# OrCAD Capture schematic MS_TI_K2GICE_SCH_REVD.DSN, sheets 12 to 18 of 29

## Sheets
12 P12_K2G_ICE_SPI_FLASH: size C; title: QSPI_FLASH
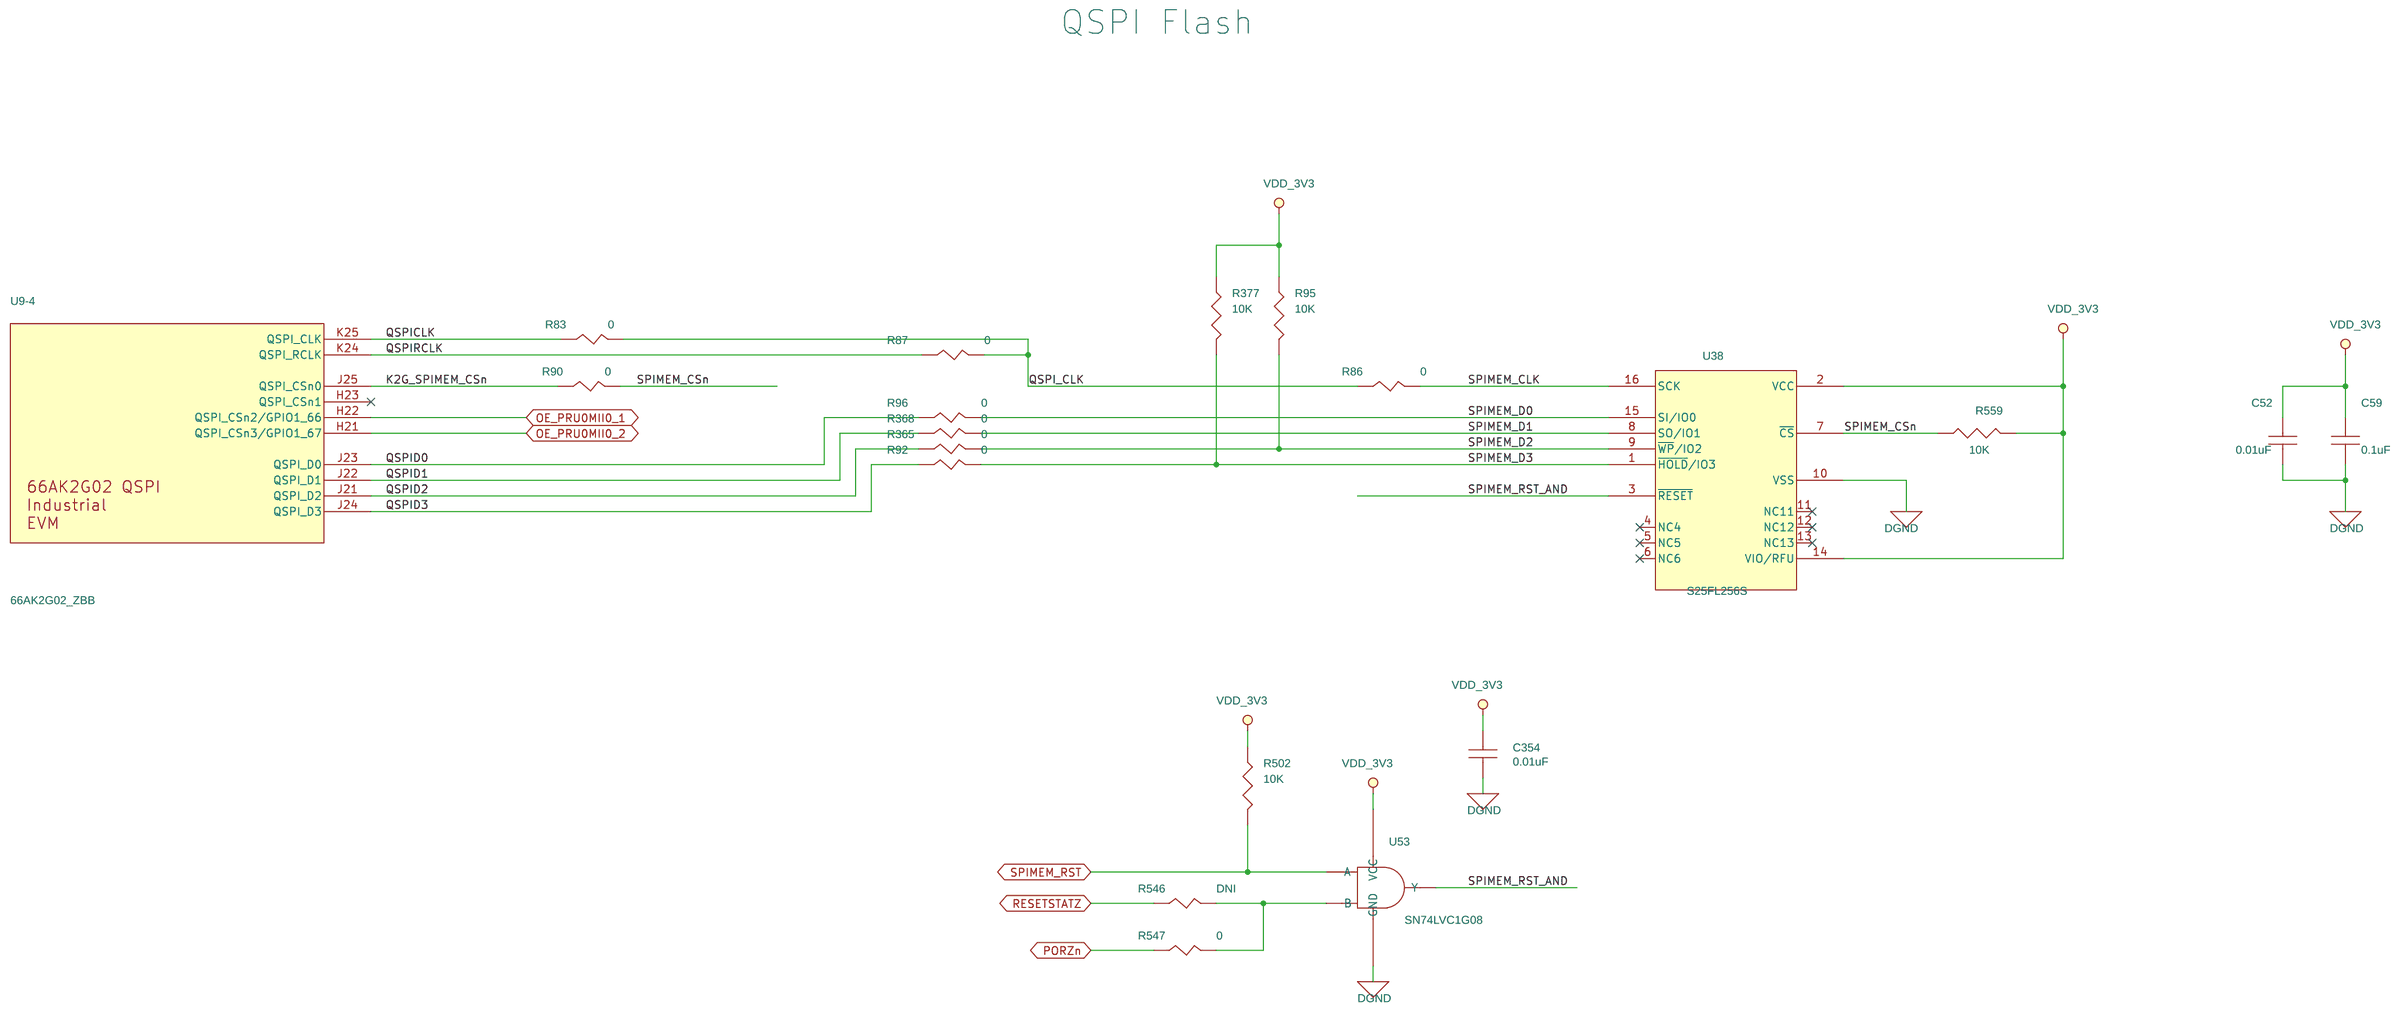
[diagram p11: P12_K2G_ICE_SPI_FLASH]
13 P13_K2G_ICE_GigEthernet: size C; title: GIGABIT ETHERNET
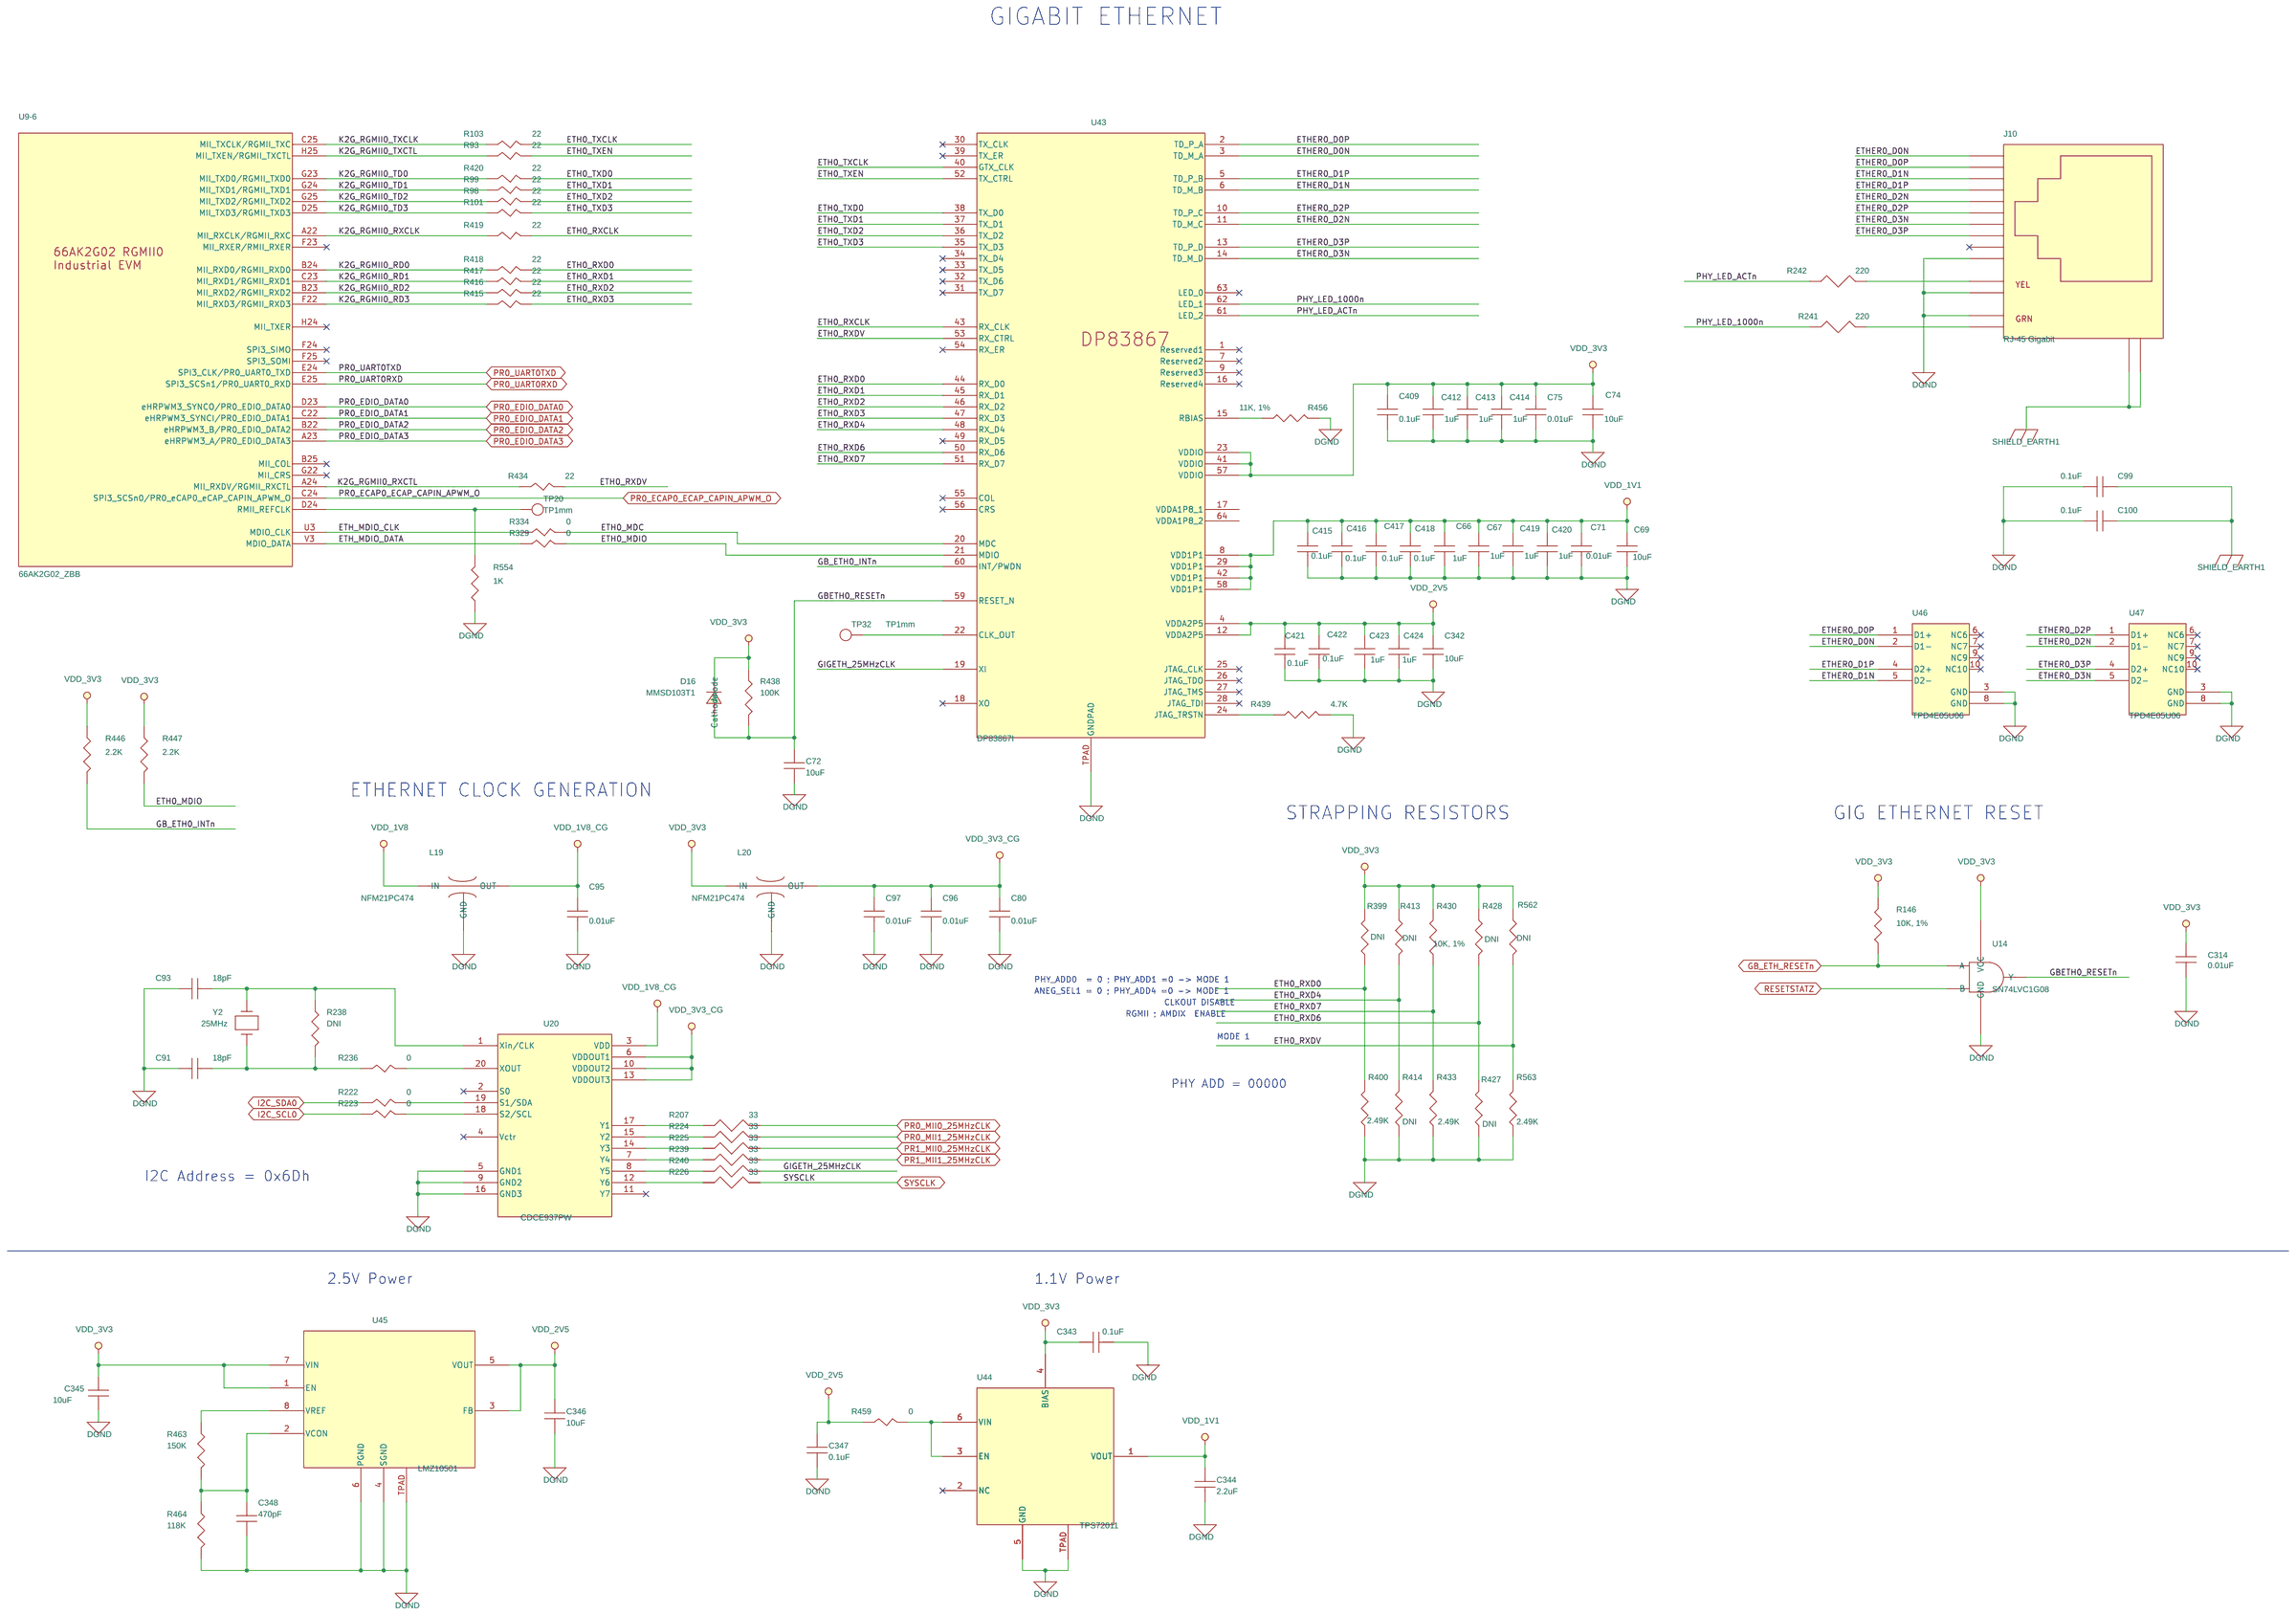
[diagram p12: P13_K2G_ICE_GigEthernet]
14 P14_K2G_ICE_PRU0MII0_Ethernet 0: size C; title: PRU0MII0_Ethernet 0
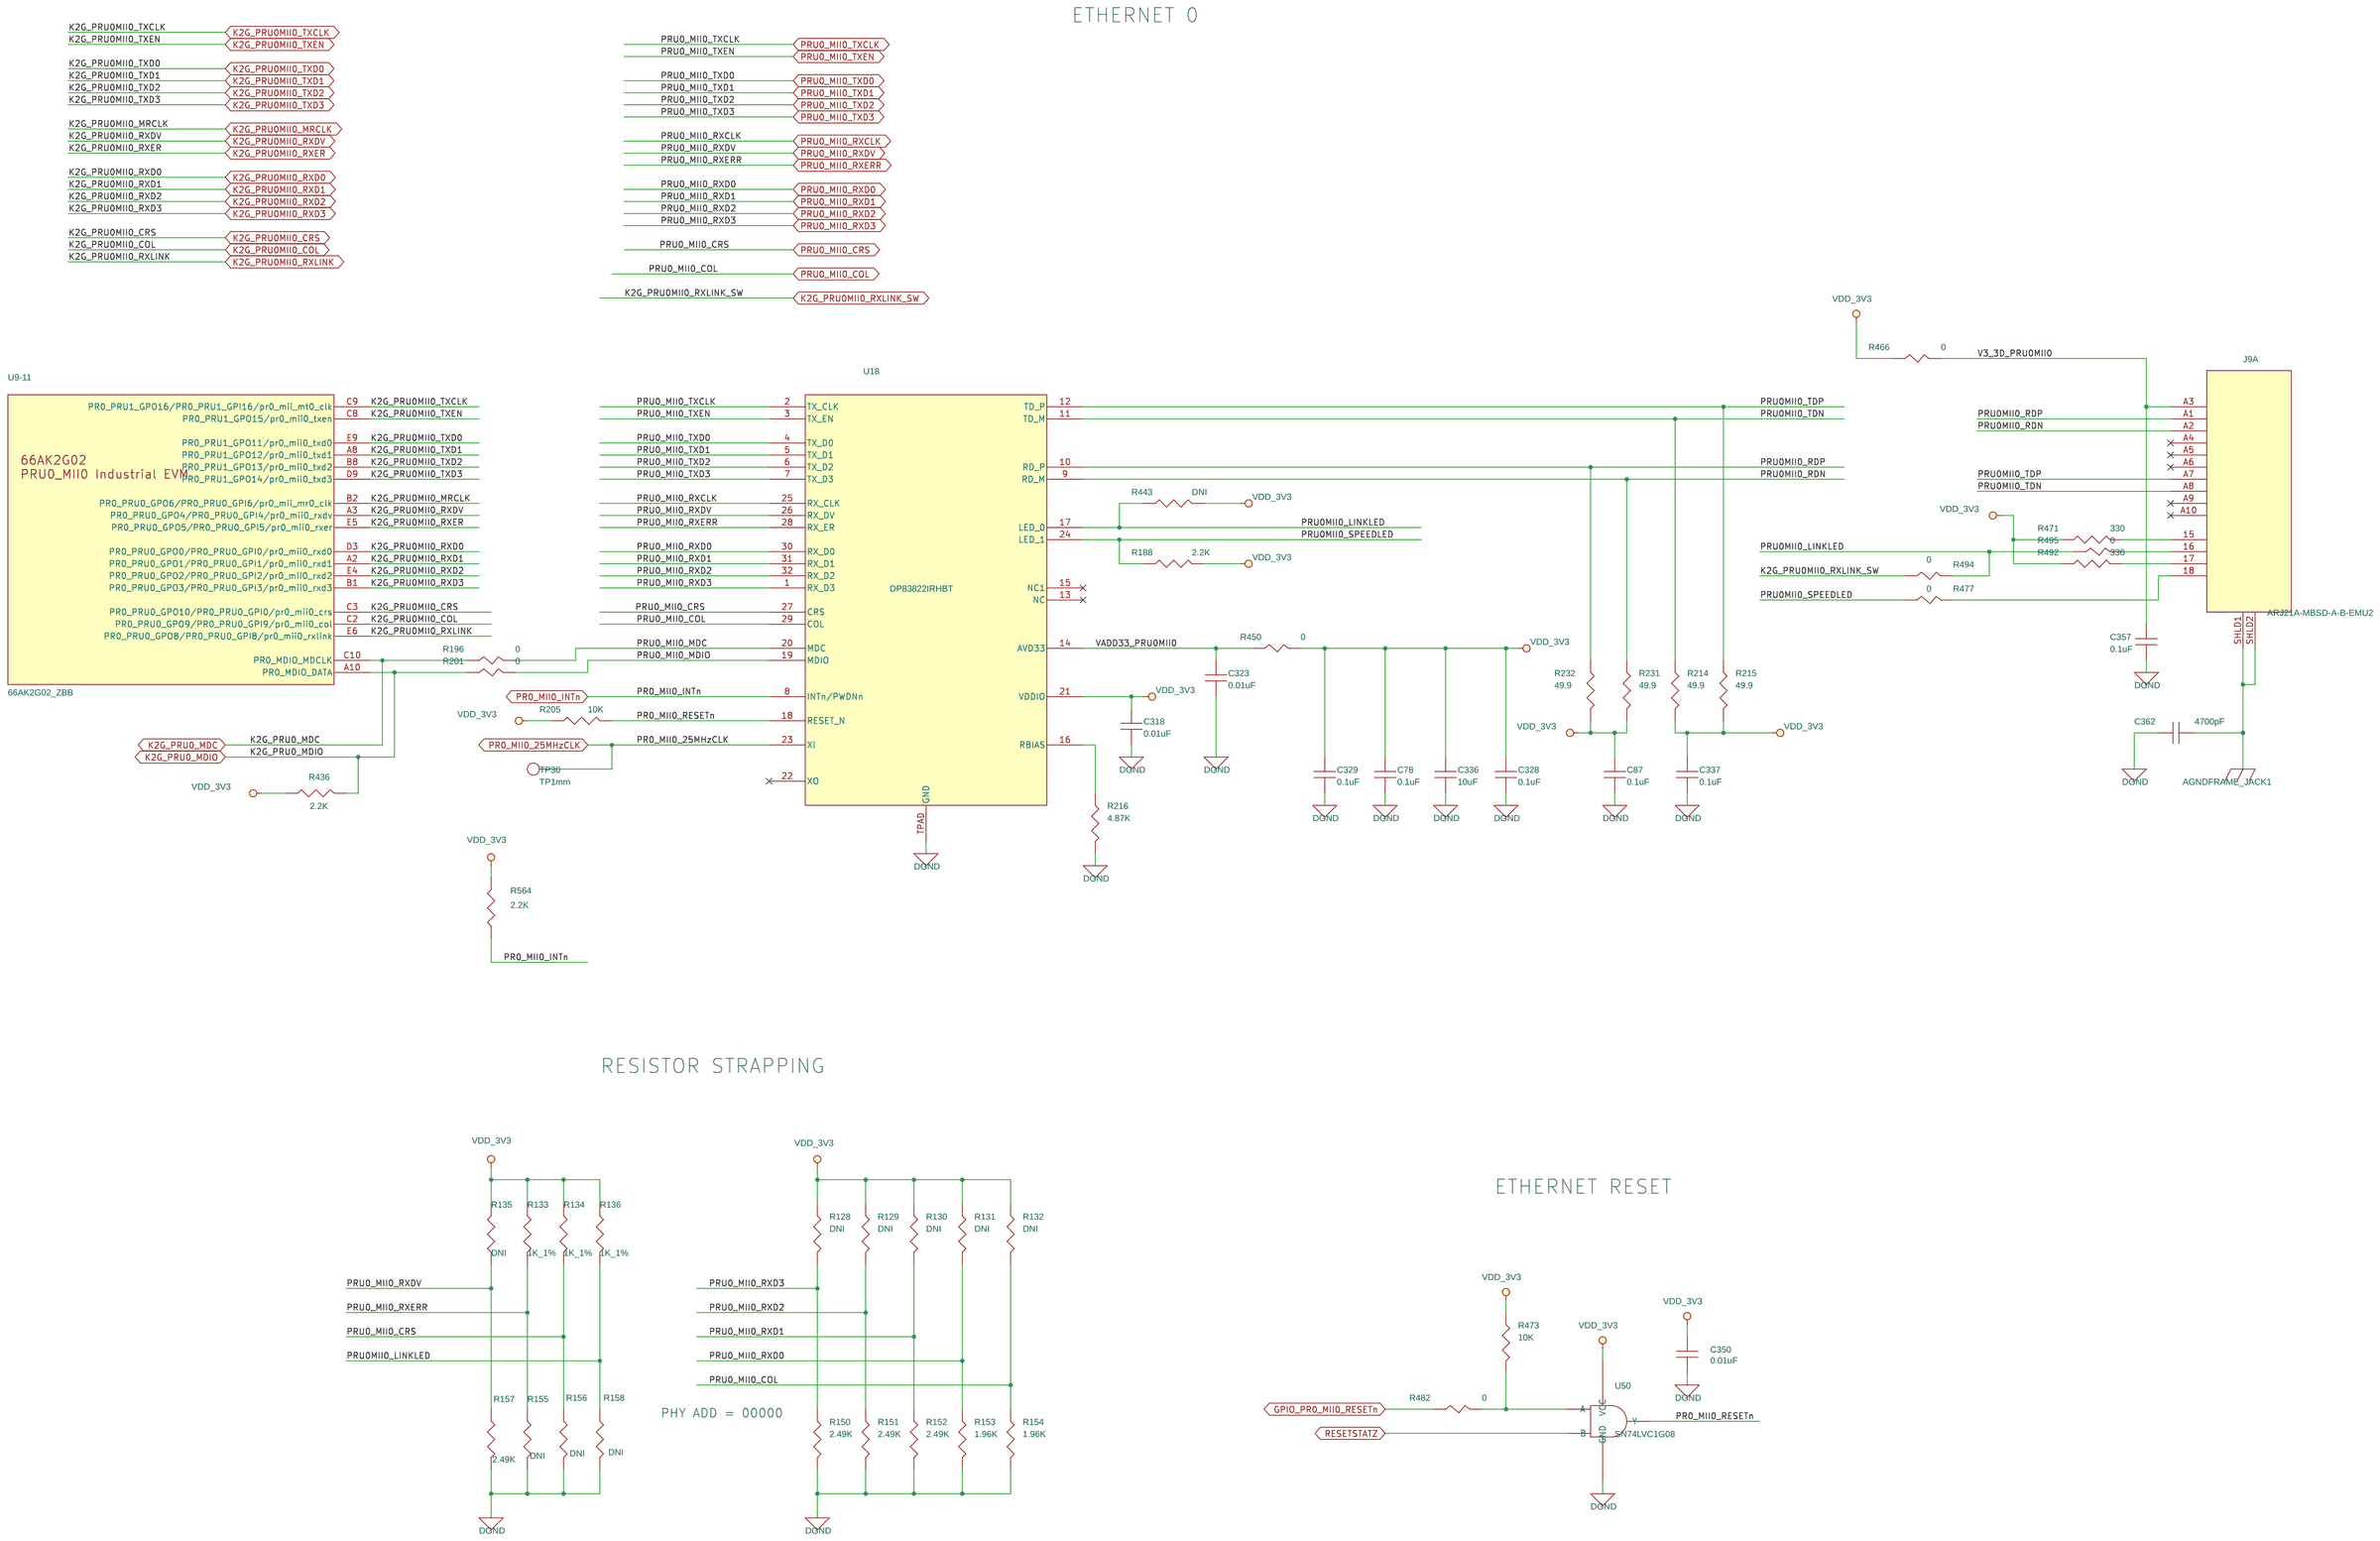
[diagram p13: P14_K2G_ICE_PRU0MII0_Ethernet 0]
15 P15_K2G_ICE_PRU0MII1_Ethernet 1: size C; title: PRU0MII1_Ethernet 1
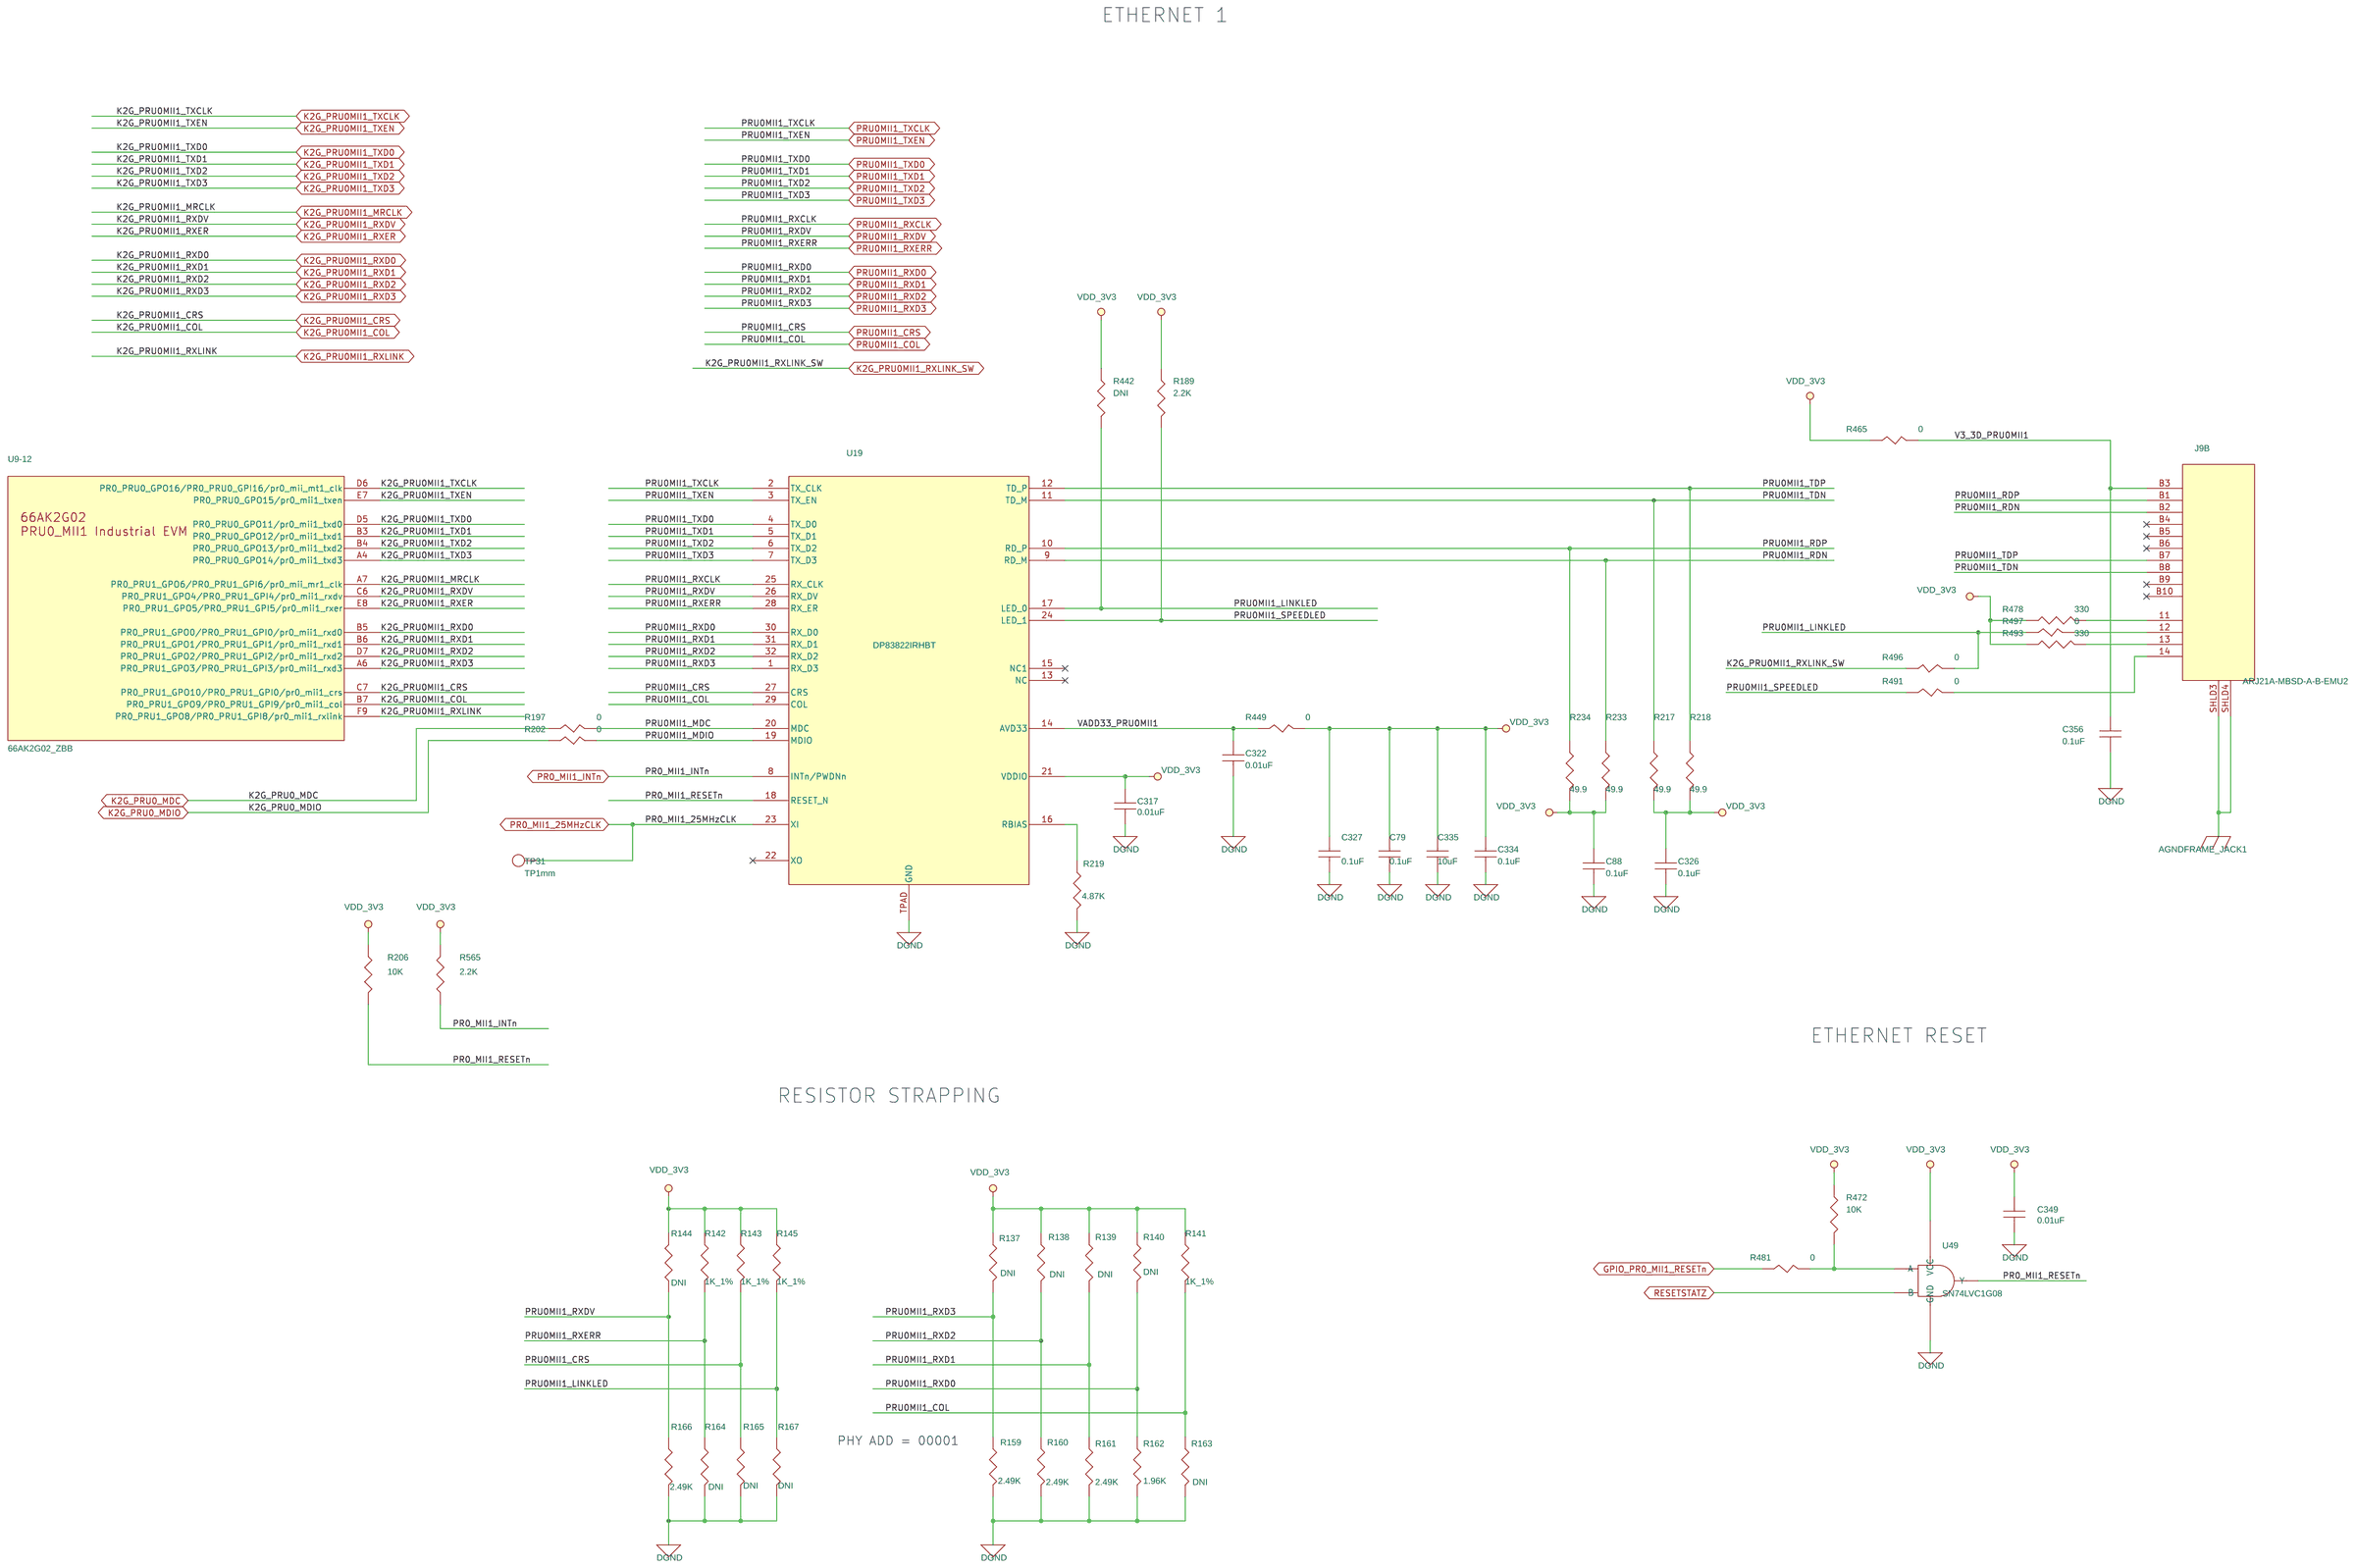
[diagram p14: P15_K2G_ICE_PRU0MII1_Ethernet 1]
16 P16_K2G_ICE_PRU1MII0_Ethernet 2: size C; title: PRU1MII0_Ethernet 2
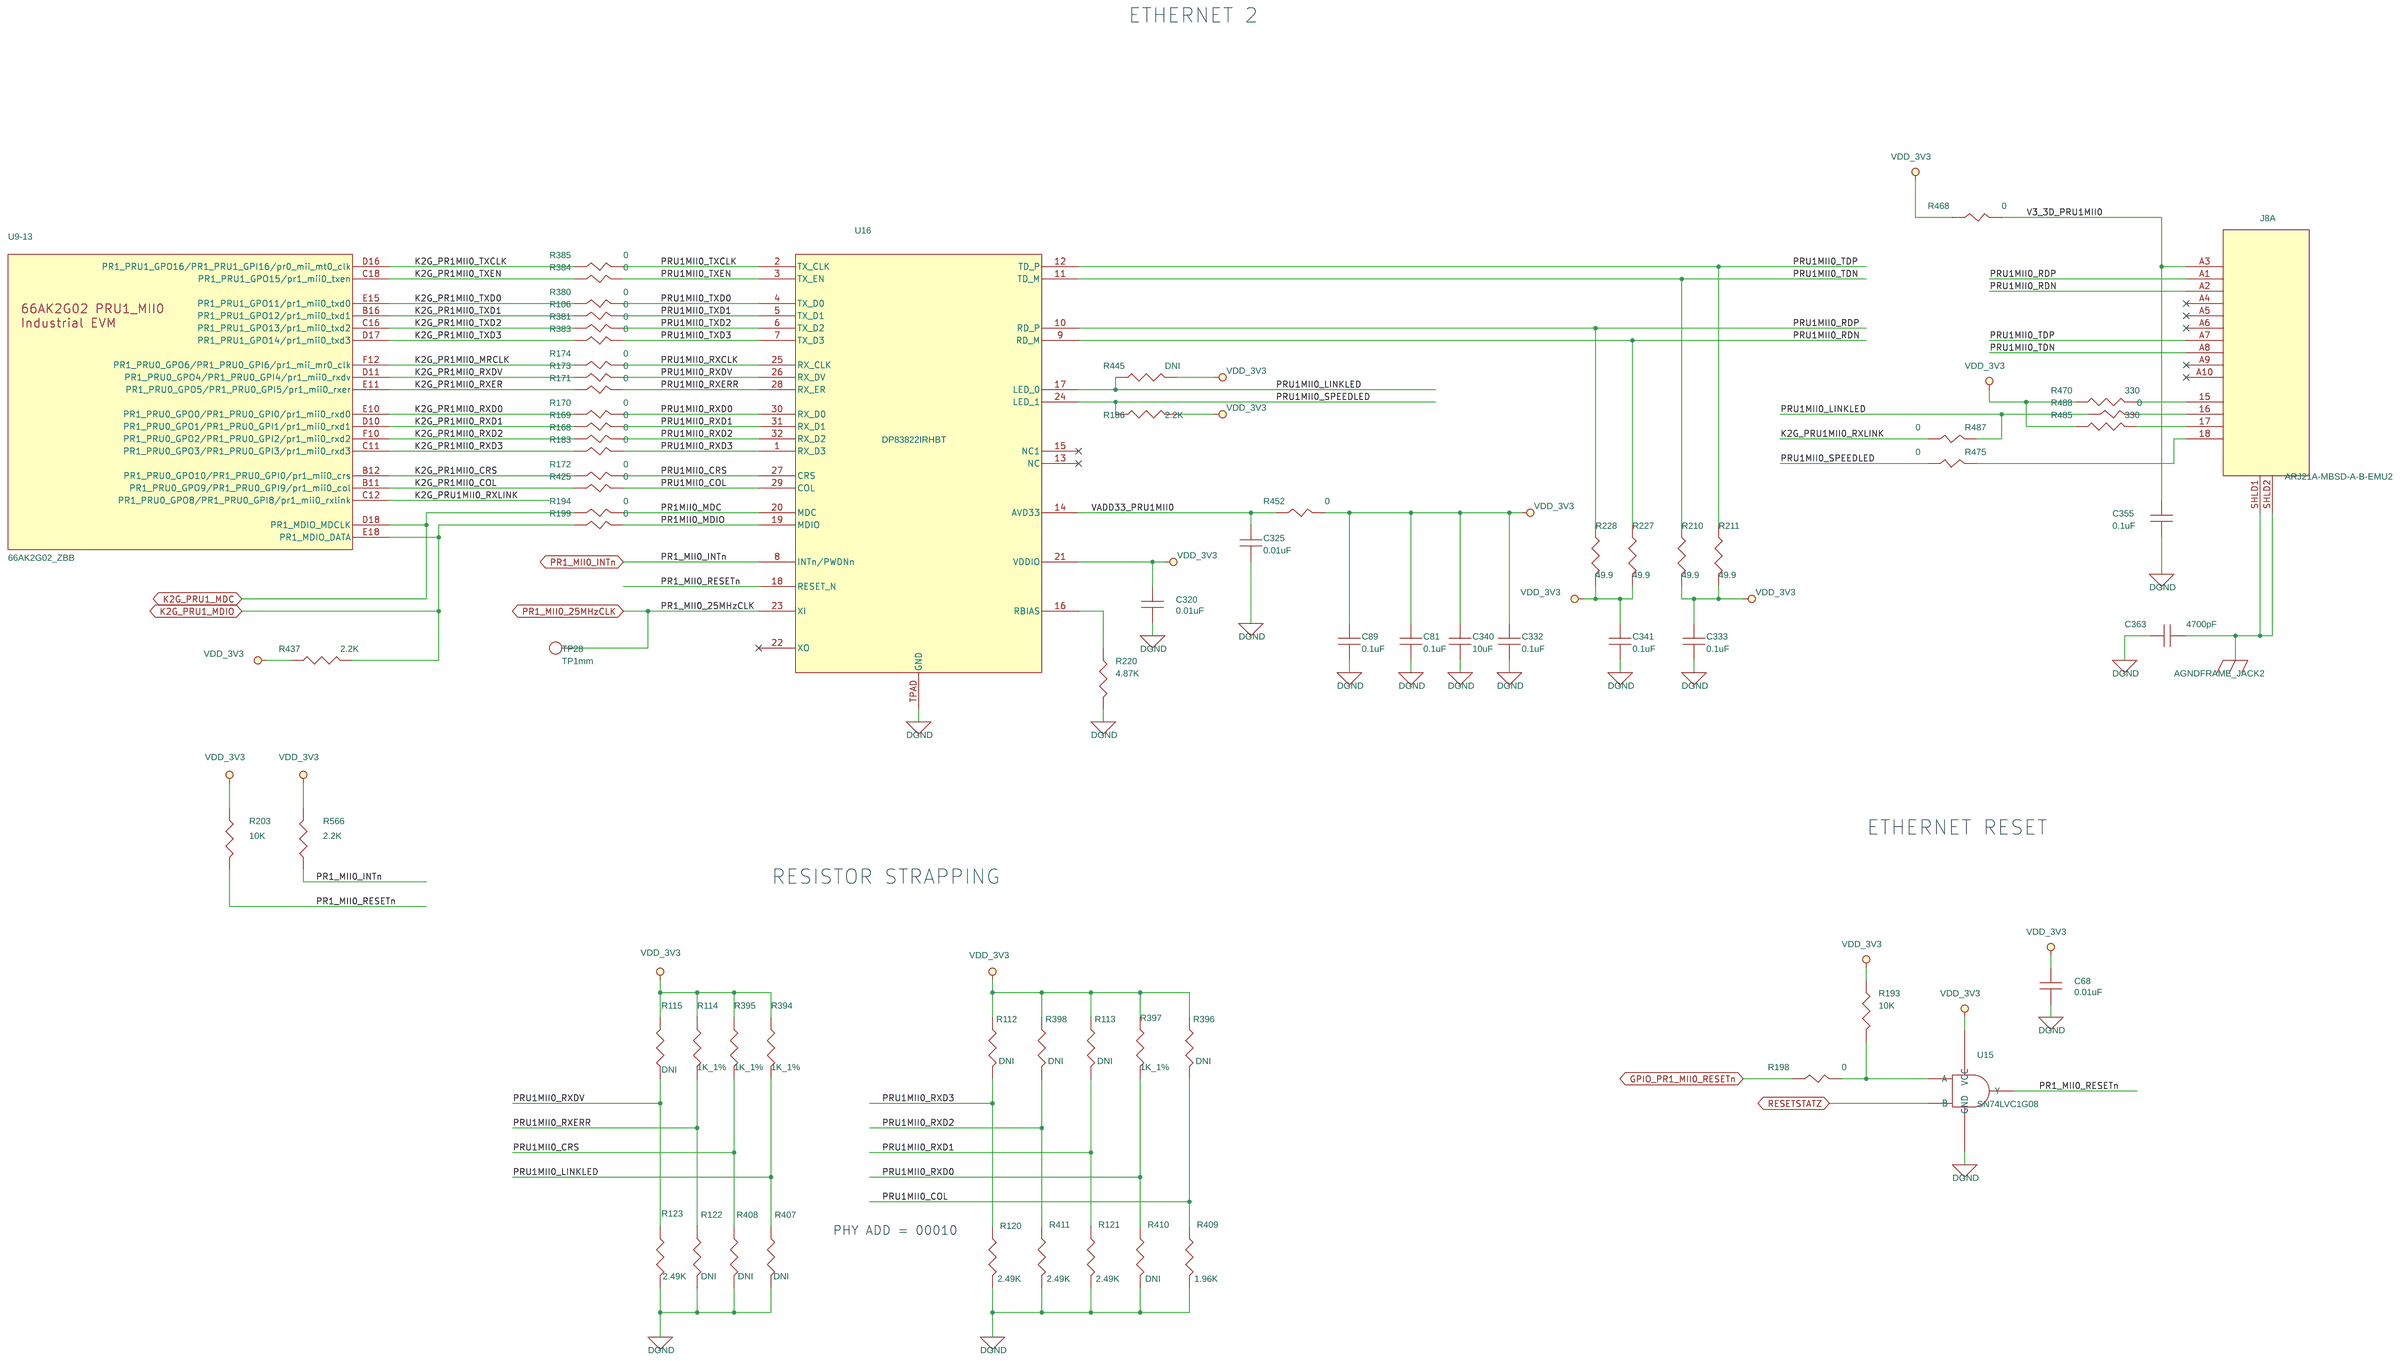
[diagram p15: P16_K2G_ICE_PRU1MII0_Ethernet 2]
17 P17_K2G_ICE_PRU1MII1_Ethernet 3: size C; title: PRU1MII1_Ethernet 3
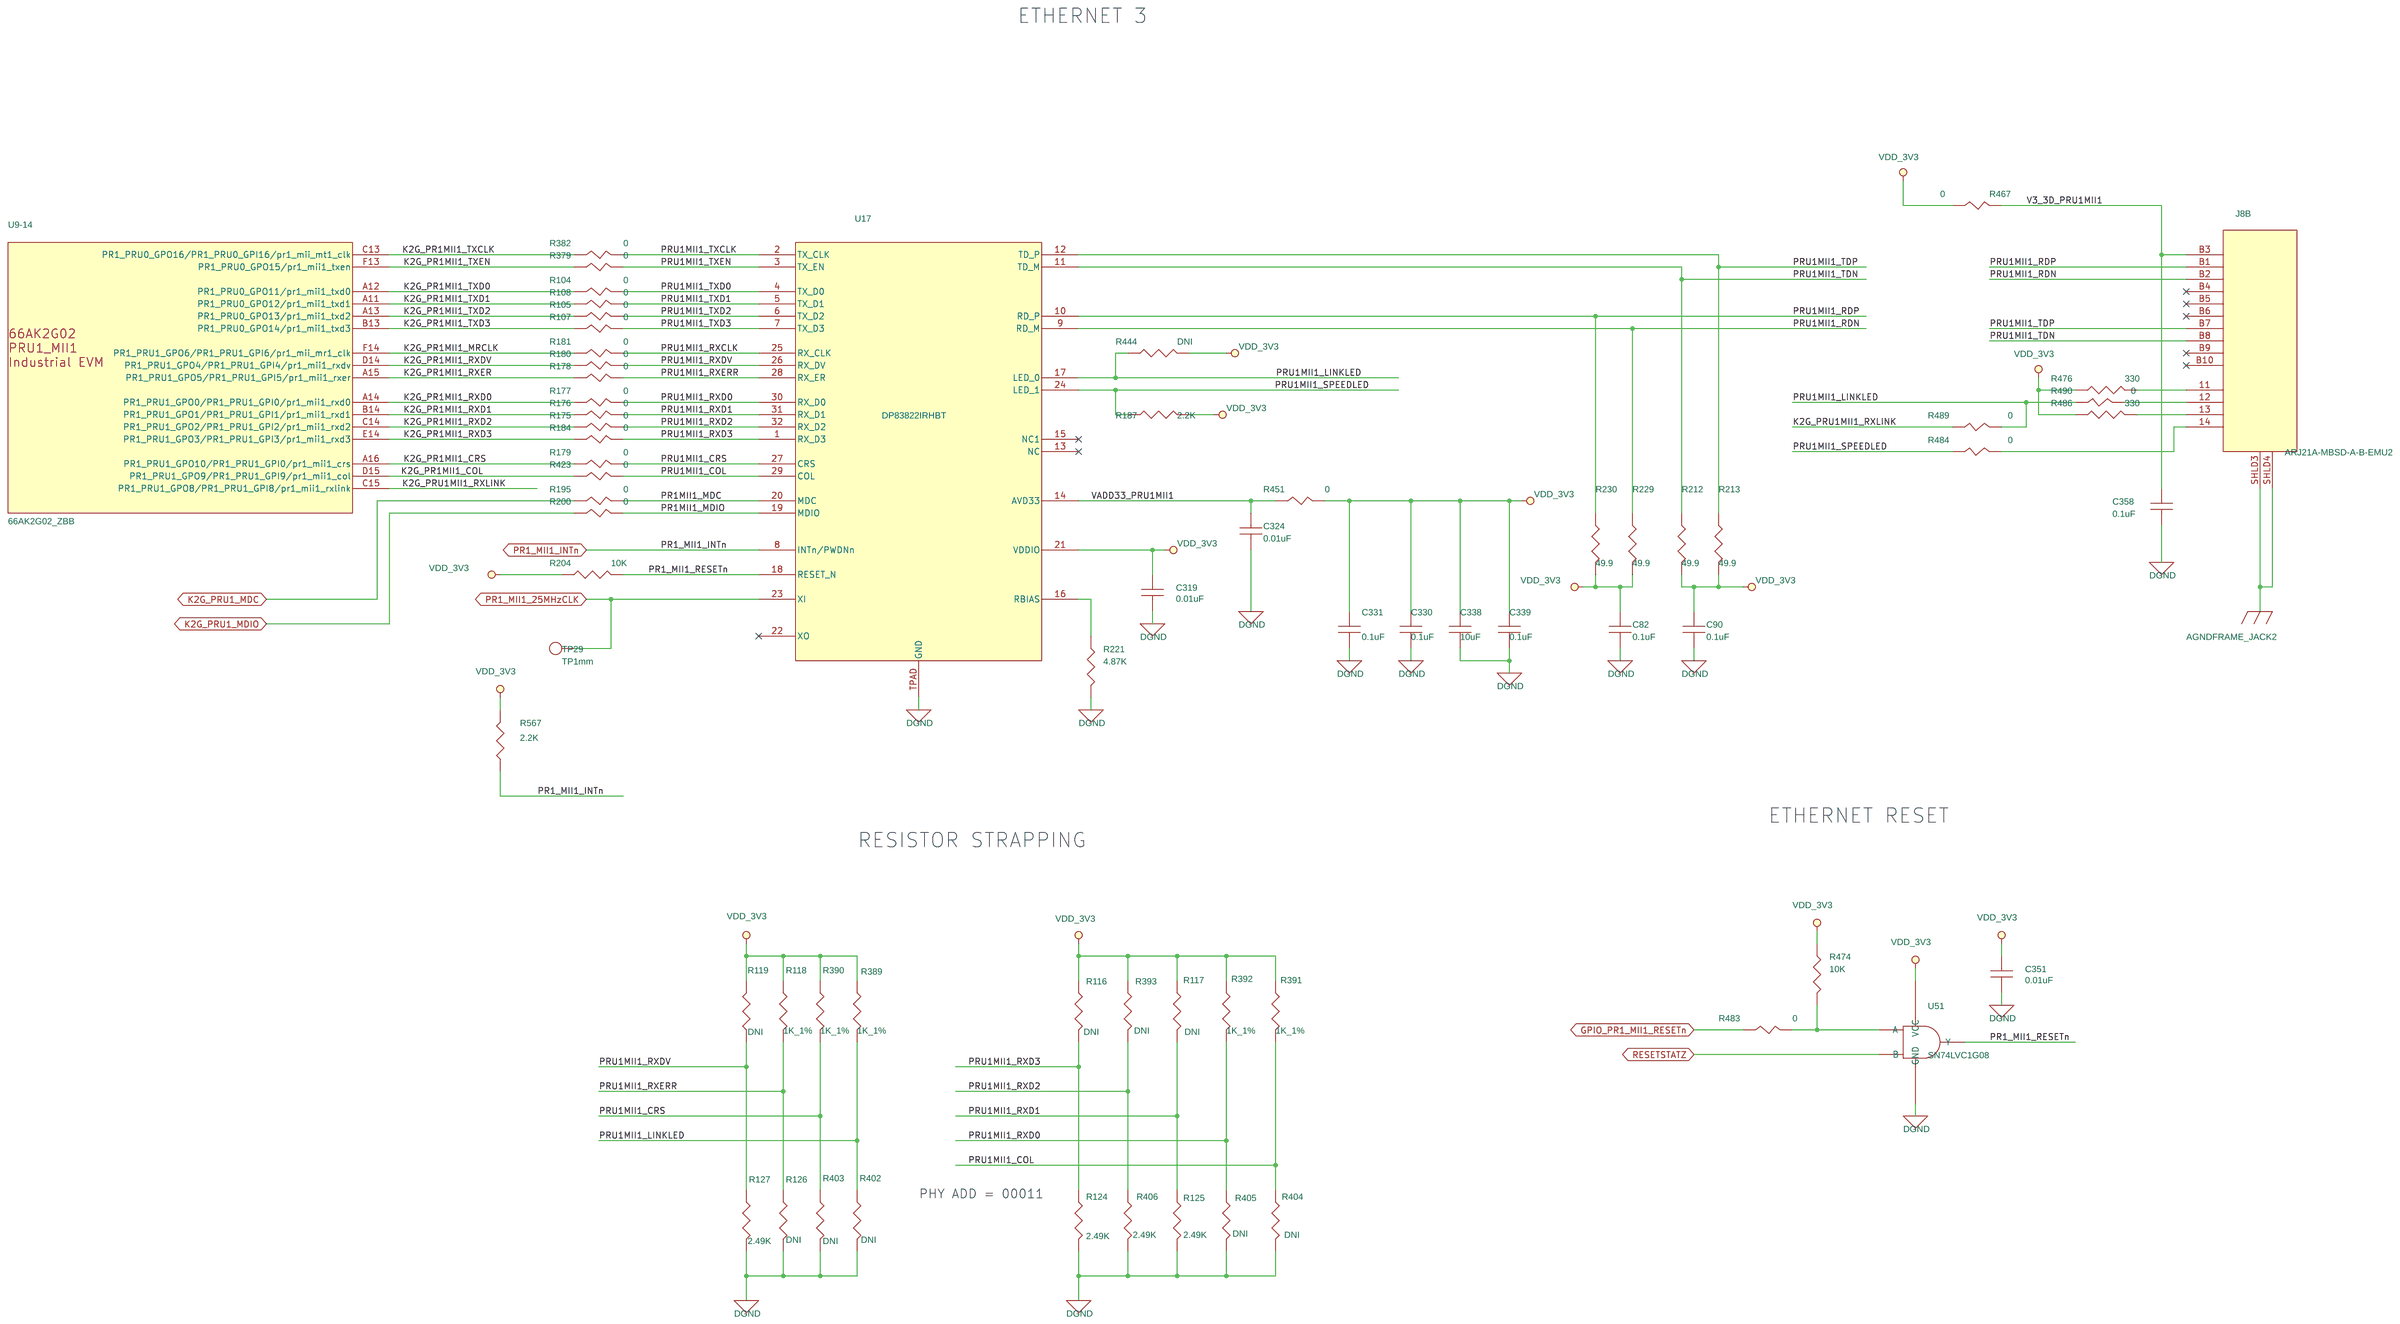
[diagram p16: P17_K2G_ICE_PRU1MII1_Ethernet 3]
18 P18_K2G_ICE_SDMMC: size C; title: SDMMC
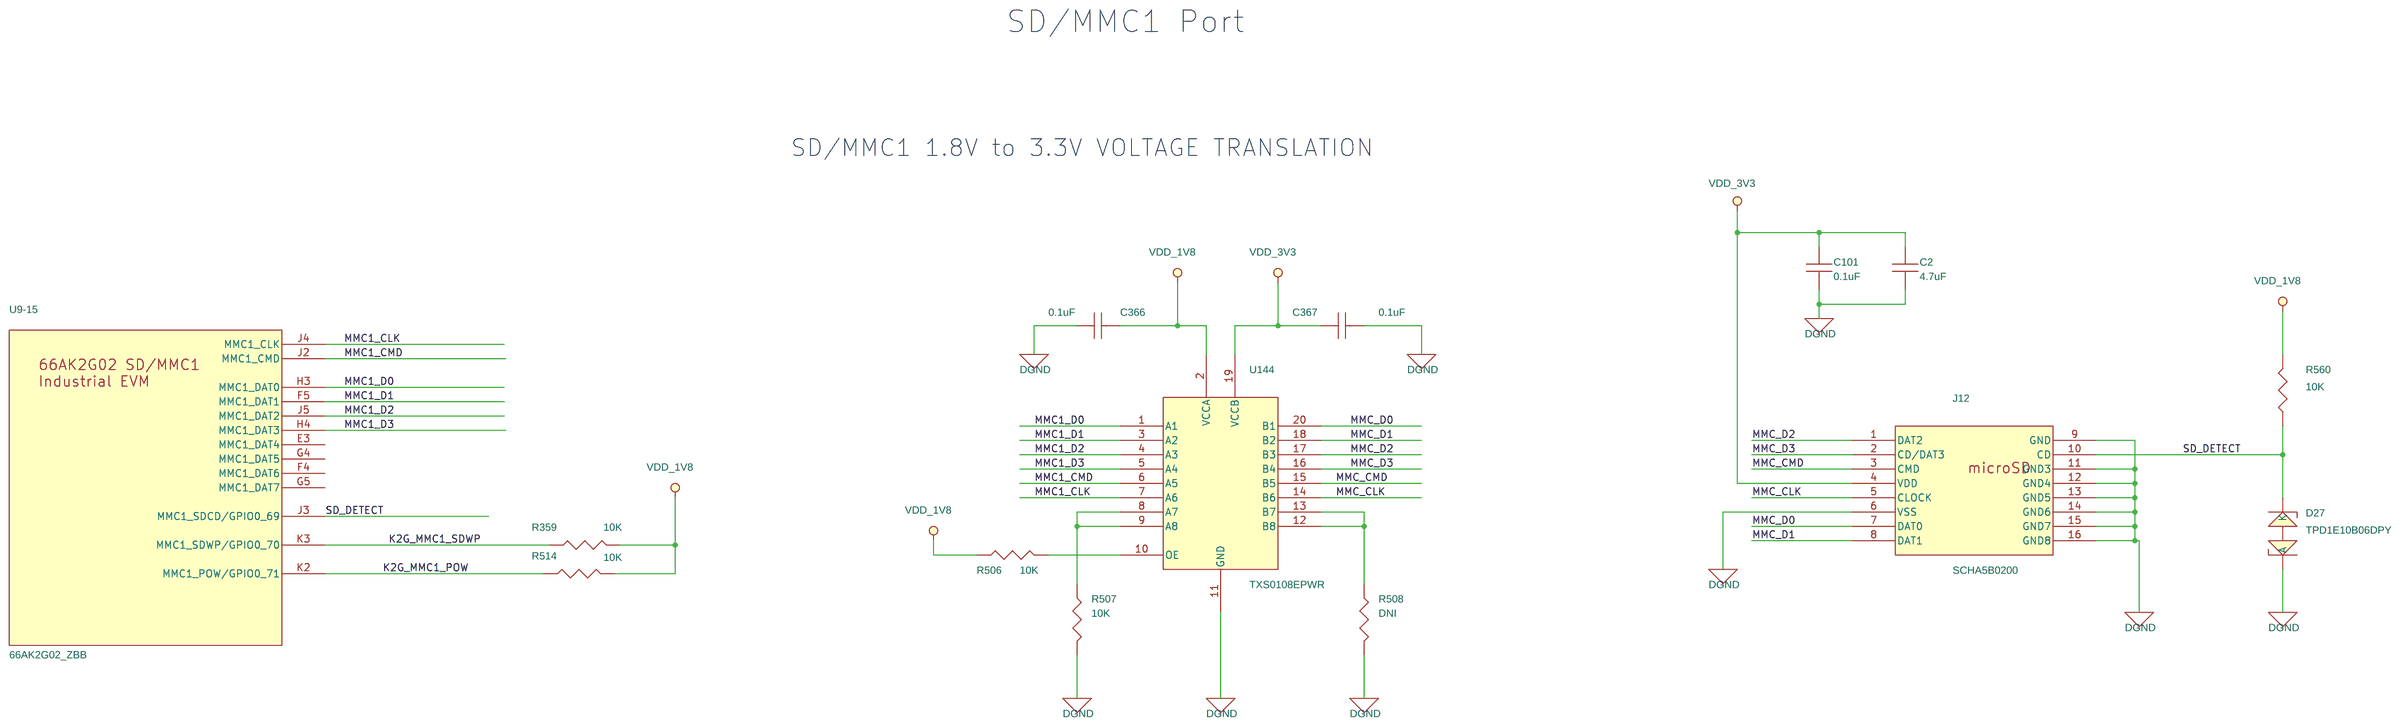
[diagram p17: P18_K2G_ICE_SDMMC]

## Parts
sheet P12_K2G_ICE_SPI_FLASH
C52  0.01uF  [SM-7351-CAP-0402]
C59  0.1uF  [SM-7351-CAP-0402]
C354  0.01uF  [SM-7351-CAP-0402]
R83  0  [SM-7351-RES-0402]
R86  0  [SM-7351-RES-0402]
R87  0  [SM-7351-RES-0402]
R90  0  [SM-7351-RES-0402]
R92  0  [SM-7351-RES-0402]
R95  10K  [SM-7351-RES-0402]
R96  0  [SM-7351-RES-0402]
R365  0  [SM-7351-RES-0402]
R368  0  [SM-7351-RES-0402]
R377  10K  [SM-7351-RES-0402]
R502  10K  [SM-7351-RES-0402]
R546  DNI  [SM-7351-RES-0402]
R547  0  [SM-7351-RES-0402]
R559  10K  [SM-7351-RES-0402]
U38  S25FL256S  [soic_16pin_dw]
U53  SN74LVC1G08  [sm-so-sc70-5]
sheet P13_K2G_ICE_GigEthernet
C66  1uF  [SM-7351-CAP-0402]
C67  1uF  [SM-7351-CAP-0402]
C69  10uF  [SM-7351-CAP-0805]
C71  0.01uF  [SM-7351-CAP-0402]
C72  10uF  [SM-7351-CAP-0805]
C74  10uF  [SM-7351-CAP-0805]
C75  0.01uF  [SM-7351-CAP-0402]
C80  0.01uF  [SM-7351-CAP-0402]
C91  18pF  [SM-7351-CAP-0402]
C93  18pF  [SM-7351-CAP-0402]
C95  0.01uF  [SM-7351-CAP-0402]
C96  0.01uF  [SM-7351-CAP-0402]
C97  0.01uF  [SM-7351-CAP-0402]
C99  0.1uF  [SM-7351-CAP-0402]
C100  0.1uF  [SM-7351-CAP-0402]
C314  0.01uF  [SM-7351-CAP-0402]
C342  10uF  [SM-7351-CAP-0805]
C343  0.1uF  [SM-7351-CAP-0402]
C344  2.2uF  [SM-7351-CAP-0603]
C345  10uF  [SM-7351-CAP-0805]
C346  10uF  [SM-7351-CAP-0805]
C347  0.1uF  [SM-7351-CAP-0402]
C348  470pF  [SM-7351-CAP-0402]
C409  0.1uF  [SM-7351-CAP-0402]
C412  1uF  [SM-7351-CAP-0402]
C413  1uF  [SM-7351-CAP-0402]
C414  1uF  [SM-7351-CAP-0402]
C415  0.1uF  [SM-7351-CAP-0402]
C416  0.1uF  [SM-7351-CAP-0402]
C417  0.1uF  [SM-7351-CAP-0402]
C418  0.1uF  [SM-7351-CAP-0402]
C419  1uF  [SM-7351-CAP-0402]
C420  1uF  [SM-7351-CAP-0402]
C421  0.1uF  [SM-7351-CAP-0402]
C422  0.1uF  [SM-7351-CAP-0402]
C423  1uF  [SM-7351-CAP-0402]
C424  1uF  [SM-7351-CAP-0402]
D16  MMSD103T1  [sod-123]
J10  RJ-45 Gigabit  [CNRJ45-1X1WLED-598M]
L19  NFM21PC474  [FILT-NFM21PC]
L20  NFM21PC474  [FILT-NFM21PC]
R93  22  [SM-7351-RES-0402]
R98  22  [SM-7351-RES-0402]
R99  22  [SM-7351-RES-0402]
R101  22  [SM-7351-RES-0402]
R103  22  [SM-7351-RES-0402]
R146  10K, 1%  [SM-7351-RES-0402]
R207  33  [SM-7351-RES-0402]
R222  0  [SM-7351-RES-0402]
R223  0  [SM-7351-RES-0402]
R224  33  [SM-7351-RES-0402]
R225  33  [SM-7351-RES-0402]
R226  33  [SM-7351-RES-0402]
R236  0  [SM-7351-RES-0402]
R238  DNI  [SM-7351-RES-0402]
R239  33  [SM-7351-RES-0402]
R240  33  [SM-7351-RES-0402]
R241  220  [SM-7351-RES-0402]
R242  220  [SM-7351-RES-0402]
R329  0  [SM-7351-RES-0402]
R334  0  [SM-7351-RES-0402]
R399  DNI  [SM-7351-RES-0402]
R400  2.49K  [SM-7351-RES-0402]
R413  DNI  [SM-7351-RES-0402]
R414  DNI  [SM-7351-RES-0402]
R415  22  [SM-7351-RES-0402]
R416  22  [SM-7351-RES-0402]
R417  22  [SM-7351-RES-0402]
R418  22  [SM-7351-RES-0402]
R419  22  [SM-7351-RES-0402]
R420  22  [SM-7351-RES-0402]
R427  DNI  [SM-7351-RES-0402]
R428  DNI  [SM-7351-RES-0402]
R430  10K, 1%  [SM-7351-RES-0402]
R433  2.49K  [SM-7351-RES-0402]
R434  22  [SM-7351-RES-0402]
R438  100K  [SM-7351-RES-0402]
R439  4.7K  [SM-7351-RES-0402]
R446  2.2K  [sm-7351-res-0402]
R447  2.2K  [sm-7351-res-0402]
R456  11K, 1%  [SM-7351-RES-0402]
R459  0  [SM-7351-RES-1210]
R463  150K  [SM-7351-RES-0402]
R464  118K  [SM-7351-RES-0402]
R554  1K  [SM-7351-RES-0402]
R562  DNI  [SM-7351-RES-0402]
R563  2.49K  [SM-7351-RES-0402]
TP20  TP1mm  [tp_smd1mmcircle]
TP32  TP1mm  [tp_smd1mmcircle]
U14  SN74LVC1G08  [sm-so-sc70-5]
U20  CDCE937PW  [U_20_PW]
U43  DP83867I  [QFP10X10-64-47M]
U44  TPS72011  [SON2X2-6]
U45  LMZ10501  [LLP3X2-8-59M]
U46  TPD4E05U06  [USON2X1-10-22M]
U47  TPD4E05U06  [USON2X1-10-22M]
Y2  25MHz  [SM_OSC_ABM3]
sheet P14_K2G_ICE_PRU0MII0_Ethernet 0
C78  0.1uF  [SM-7351-CAP-0402]
C87  0.1uF  [SM-7351-CAP-0402]
C318  0.01uF  [SM-7351-CAP-0402]
C323  0.01uF  [SM-7351-CAP-0402]
C328  0.1uF  [SM-7351-CAP-0402]
C329  0.1uF  [SM-7351-CAP-0402]
C336  10uF  [SM-7351-CAP-0805]
C337  0.1uF  [SM-7351-CAP-0402]
C350  0.01uF  [SM-7351-CAP-0402]
C357  0.1uF  [SM-7351-CAP-0402]
C362  4700pF  [SM-7351-CAP-0402]
J9  ARJ21A-MBSD-A-B-EMU2  [CNARJ21A-MB]  (sections A,B)
R128  DNI  [SM-7351-RES-0402]
R129  DNI  [SM-7351-RES-0402]
R130  DNI  [RES0402]
R131  DNI  [SM-7351-RES-0402]
R132  DNI  [SM-7351-RES-0402]
R133  1K_1%  [SM-7351-RES-0402]
R134  1K_1%  [SM-7351-RES-0402]
R135  DNI  [SM-7351-RES-0402]
R136  1K_1%  [SM-7351-RES-0402]
R150  2.49K  [SM-7351-RES-0402]
R151  2.49K  [SM-7351-RES-0402]
R152  2.49K  [SM-7351-RES-0402]
R153  1.96K  [SM-7351-RES-0402]
R154  1.96K  [SM-7351-RES-0402]
R155  DNI  [SM-7351-RES-0402]
R156  DNI  [SM-7351-RES-0402]
R157  2.49K  [SM-7351-RES-0402]
R158  DNI  [SM-7351-RES-0402]
R188  2.2K  [sm-7351-res-0402]
R196  0  [SM-7351-RES-0402]
R201  0  [SM-7351-RES-0402]
R205  10K  [SM-7351-RES-0402]
R214  49.9  [SM-7351-RES-0402]
R215  49.9  [SM-7351-RES-0402]
R216  4.87K  [SM-7351-RES-0402]
R231  49.9  [SM-7351-RES-0402]
R232  49.9  [SM-7351-RES-0402]
R436  2.2K  [sm-7351-res-0402]
R443  DNI  [sm-7351-res-0402]
R450  0  [SM-7351-RES-0603]
R466  0  [SM-7351-RES-0402]
R471  330  [SM-7351-RES-0402]
R473  10K  [SM-7351-RES-0402]
R477  0  [SM-7351-RES-0402]
R482  0  [SM-7351-RES-0402]
R492  330  [SM-7351-RES-0402]
R494  0  [SM-7351-RES-0402]
R495  0  [SM-7351-RES-0402]
R564  2.2K  [sm-7351-res-0402]
TP30  TP1mm  [tp_smd1mmcircle]
U18  DP83822IRHBT  [qfn5x5-32-39m]
U50  SN74LVC1G08  [sm-so-sc70-5]
sheet P15_K2G_ICE_PRU0MII1_Ethernet 1
C79  0.1uF  [SM-7351-CAP-0402]
C88  0.1uF  [SM-7351-CAP-0402]
C317  0.01uF  [SM-7351-CAP-0402]
C322  0.01uF  [SM-7351-CAP-0402]
C326  0.1uF  [SM-7351-CAP-0402]
C327  0.1uF  [SM-7351-CAP-0402]
C334  0.1uF  [SM-7351-CAP-0402]
C335  10uF  [SM-7351-CAP-0805]
C349  0.01uF  [SM-7351-CAP-0402]
C356  0.1uF  [SM-7351-CAP-0402]
R137  DNI  [SM-7351-RES-0402]
R138  DNI  [SM-7351-RES-0402]
R139  DNI  [RES0402]
R140  DNI  [SM-7351-RES-0402]
R141  1K_1%  [SM-7351-RES-0402]
R142  1K_1%  [SM-7351-RES-0402]
R143  1K_1%  [SM-7351-RES-0402]
R144  DNI  [SM-7351-RES-0402]
R145  1K_1%  [SM-7351-RES-0402]
R159  2.49K  [SM-7351-RES-0402]
R160  2.49K  [SM-7351-RES-0402]
R161  2.49K  [SM-7351-RES-0402]
R162  1.96K  [SM-7351-RES-0402]
R163  DNI  [SM-7351-RES-0402]
R164  DNI  [SM-7351-RES-0402]
R165  DNI  [SM-7351-RES-0402]
R166  2.49K  [SM-7351-RES-0402]
R167  DNI  [SM-7351-RES-0402]
R189  2.2K  [sm-7351-res-0402]
R197  0  [SM-7351-RES-0402]
R202  0  [SM-7351-RES-0402]
R206  10K  [SM-7351-RES-0402]
R217  49.9  [SM-7351-RES-0402]
R218  49.9  [SM-7351-RES-0402]
R219  4.87K  [SM-7351-RES-0402]
R233  49.9  [SM-7351-RES-0402]
R234  49.9  [SM-7351-RES-0402]
R442  DNI  [sm-7351-res-0402]
R449  0  [SM-7351-RES-0603]
R465  0  [SM-7351-RES-0402]
R472  10K  [SM-7351-RES-0402]
R478  330  [SM-7351-RES-0402]
R481  0  [SM-7351-RES-0402]
R491  0  [SM-7351-RES-0402]
R493  330  [SM-7351-RES-0402]
R496  0  [SM-7351-RES-0402]
R497  0  [SM-7351-RES-0402]
R565  2.2K  [sm-7351-res-0402]
TP31  TP1mm  [tp_smd1mmcircle]
U19  DP83822IRHBT  [qfn5x5-32-39m]
U49  SN74LVC1G08  [sm-so-sc70-5]
sheet P16_K2G_ICE_PRU1MII0_Ethernet 2
C68  0.01uF  [SM-7351-CAP-0402]
C81  0.1uF  [SM-7351-CAP-0402]
C89  0.1uF  [SM-7351-CAP-0402]
C320  0.01uF  [SM-7351-CAP-0402]
C325  0.01uF  [SM-7351-CAP-0402]
C332  0.1uF  [SM-7351-CAP-0402]
C333  0.1uF  [SM-7351-CAP-0402]
C340  10uF  [SM-7351-CAP-0805]
C341  0.1uF  [SM-7351-CAP-0402]
C355  0.1uF  [SM-7351-CAP-0402]
C363  4700pF  [SM-7351-CAP-0402]
R106  0  [SM-7351-RES-0402]
R112  DNI  [SM-7351-RES-0402]
R113  DNI  [RES0402]
R114  1K_1%  [SM-7351-RES-0402]
R115  DNI  [SM-7351-RES-0402]
R120  2.49K  [SM-7351-RES-0402]
R121  2.49K  [SM-7351-RES-0402]
R122  DNI  [SM-7351-RES-0402]
R123  2.49K  [SM-7351-RES-0402]
R168  0  [SM-7351-RES-0402]
R169  0  [SM-7351-RES-0402]
R170  0  [SM-7351-RES-0402]
R171  0  [SM-7351-RES-0402]
R172  0  [SM-7351-RES-0402]
R173  0  [SM-7351-RES-0402]
R174  0  [SM-7351-RES-0402]
R183  0  [SM-7351-RES-0402]
R186  2.2K  [sm-7351-res-0402]
R193  10K  [SM-7351-RES-0402]
R194  0  [SM-7351-RES-0402]
R198  0  [SM-7351-RES-0402]
R199  0  [SM-7351-RES-0402]
R203  10K  [SM-7351-RES-0402]
R210  49.9  [SM-7351-RES-0402]
R211  49.9  [SM-7351-RES-0402]
R220  4.87K  [SM-7351-RES-0402]
R227  49.9  [SM-7351-RES-0402]
R228  49.9  [SM-7351-RES-0402]
R380  0  [SM-7351-RES-0402]
R381  0  [SM-7351-RES-0402]
R383  0  [SM-7351-RES-0402]
R384  0  [SM-7351-RES-0402]
R385  0  [SM-7351-RES-0402]
R394  1K_1%  [SM-7351-RES-0402]
R395  1K_1%  [SM-7351-RES-0402]
R396  DNI  [SM-7351-RES-0402]
R397  1K_1%  [SM-7351-RES-0402]
R398  DNI  [SM-7351-RES-0402]
R407  DNI  [SM-7351-RES-0402]
R408  DNI  [SM-7351-RES-0402]
R409  1.96K  [SM-7351-RES-0402]
R410  DNI  [SM-7351-RES-0402]
R411  2.49K  [SM-7351-RES-0402]
R425  0  [SM-7351-RES-0402]
R437  2.2K  [sm-7351-res-0402]
R445  DNI  [sm-7351-res-0402]
R452  0  [SM-7351-RES-0603]
R468  0  [SM-7351-RES-0402]
R470  330  [SM-7351-RES-0402]
R475  0  [SM-7351-RES-0402]
R485  330  [SM-7351-RES-0402]
R487  0  [SM-7351-RES-0402]
R488  0  [SM-7351-RES-0402]
R566  2.2K  [sm-7351-res-0402]
TP28  TP1mm  [tp_smd1mmcircle]
U15  SN74LVC1G08  [sm-so-sc70-5]
U16  DP83822IRHBT  [qfn5x5-32-39m]
sheet P17_K2G_ICE_PRU1MII1_Ethernet 3
C82  0.1uF  [SM-7351-CAP-0402]
C90  0.1uF  [SM-7351-CAP-0402]
C319  0.01uF  [SM-7351-CAP-0402]
C324  0.01uF  [SM-7351-CAP-0402]
C330  0.1uF  [SM-7351-CAP-0402]
C331  0.1uF  [SM-7351-CAP-0402]
C338  10uF  [SM-7351-CAP-0805]
C339  0.1uF  [SM-7351-CAP-0402]
C351  0.01uF  [SM-7351-CAP-0402]
C358  0.1uF  [SM-7351-CAP-0402]
J8  ARJ21A-MBSD-A-B-EMU2  [CNARJ21A-MB]  (sections A,B)
R104  0  [SM-7351-RES-0402]
R105  0  [SM-7351-RES-0402]
R107  0  [SM-7351-RES-0402]
R108  0  [SM-7351-RES-0402]
R116  DNI  [SM-7351-RES-0402]
R117  DNI  [RES0402]
R118  1K_1%  [SM-7351-RES-0402]
R119  DNI  [SM-7351-RES-0402]
R124  2.49K  [SM-7351-RES-0402]
R125  2.49K  [SM-7351-RES-0402]
R126  DNI  [SM-7351-RES-0402]
R127  2.49K  [SM-7351-RES-0402]
R175  0  [SM-7351-RES-0402]
R176  0  [SM-7351-RES-0402]
R177  0  [SM-7351-RES-0402]
R178  0  [SM-7351-RES-0402]
R179  0  [SM-7351-RES-0402]
R180  0  [SM-7351-RES-0402]
R181  0  [SM-7351-RES-0402]
R184  0  [SM-7351-RES-0402]
R187  2.2K  [sm-7351-res-0402]
R195  0  [SM-7351-RES-0402]
R200  0  [SM-7351-RES-0402]
R204  10K  [SM-7351-RES-0402]
R212  49.9  [SM-7351-RES-0402]
R213  49.9  [SM-7351-RES-0402]
R221  4.87K  [SM-7351-RES-0402]
R229  49.9  [SM-7351-RES-0402]
R230  49.9  [SM-7351-RES-0402]
R379  0  [SM-7351-RES-0402]
R382  0  [SM-7351-RES-0402]
R389  1K_1%  [SM-7351-RES-0402]
R390  1K_1%  [SM-7351-RES-0402]
R391  1K_1%  [SM-7351-RES-0402]
R392  1K_1%  [SM-7351-RES-0402]
R393  DNI  [SM-7351-RES-0402]
R402  DNI  [SM-7351-RES-0402]
R403  DNI  [SM-7351-RES-0402]
R404  DNI  [SM-7351-RES-0402]
R405  DNI  [SM-7351-RES-0402]
R406  2.49K  [SM-7351-RES-0402]
R423  0  [SM-7351-RES-0402]
R444  DNI  [sm-7351-res-0402]
R451  0  [SM-7351-RES-0603]
R467  0  [SM-7351-RES-0402]
R474  10K  [SM-7351-RES-0402]
R476  330  [SM-7351-RES-0402]
R483  0  [SM-7351-RES-0402]
R484  0  [SM-7351-RES-0402]
R486  330  [SM-7351-RES-0402]
R489  0  [SM-7351-RES-0402]
R490  0  [SM-7351-RES-0402]
R567  2.2K  [sm-7351-res-0402]
TP29  TP1mm  [tp_smd1mmcircle]
U9  66AK2G02_ZBB  [BGA21X21-625-67M]  (sections -1,-10,-11,-12,-13,-14,-15,-16,-17,-18,-19,-2,-20,-21,-22,-23,-24,-25,-26,-27,-28,-3,-4,-5,-6,-7,-8,-9)
U17  DP83822IRHBT  [qfn5x5-32-39m]
U51  SN74LVC1G08  [sm-so-sc70-5]
sheet P18_K2G_ICE_SDMMC
C2  4.7uF  [SM-7351-CAP-0603]
C101  0.1uF  [SM-7351-CAP-0402]
C366  0.1uF  [SM-7351-CAP-0402]
C367  0.1uF  [SM-7351-CAP-0402]
D27  TPD1E10B06DPY  [DIO_DFN0402]
J12  SCHA5B0200  [SD-MICRO-SCHA5B0300]
R359  10K  [SM-7351-RES-0402]
R506  10K  [SM-7351-RES-0402]
R507  10K  [SM-7351-RES-0402]
R508  DNI  [SM-7351-RES-0402]
R514  10K  [SM-7351-RES-0402]
R560  10K  [SM-7351-RES-0402]
U144  TXS0108EPWR  [TSSOP20_25-59_260X180]

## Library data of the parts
C52 C68 C71 C75 C80 C95-C97 C314 C317-C320 C322-C325 C349-C351 C354 = 1C_0.01uFCapacitor16V10%0402
C59 C78 C79 C81 C82 C87-C90 C101 C326-C334 C337 C339 C341 C343 C347 C355-C358 C366 C367 C409 C415-C418 C421 C422 = 1C_0.1uFCapacitor16V10%0402: MfrNum: C0402C104K4RACTU
R83 R86 R87 R90 R92 R96 R104-R108 R168-R181 R183 R184 R194-R202 R222 R223 R236 R329 R334 R365 R368 R379-R385 R423 R425 R465-R468 R475 R477 R481-R484 R487-R491 R494-R497 R546 R547 = 1R_ZeroOhmResistor1_16W0402
R95 R193 R203-R206 R359 R377 R472-R474 R502 R506-R508 R514 R559 R560 = 1R_10KOhmResistor1_16W0402
U38 = 1A_S25FL256S_QSPI
U14 U15 U49-U51 U53 = 1A_SN74LVC1G08DCKT_SC70: MfrNum: SN74LVC1G08DCKR
C66 C67 C412-C414 C419 C420 C423 C424 = 1C_1uFCapacitor10V10%0402
C69 C72 C74 C335 C336 C338 C340 C342 C345 C346 = 1C_10uFCapacitor16V10%0805
C91 C93 = 1C_18pFCapacitor16V10%0402: MfrNum: CGA2B2C0G1H180J050BA
C99 C100 = 1C_0.1uFCapacitor50V10%0402: MfrNum: C1005X7R1H104K050BB
C344 = 1C_2.2uFCapacitor6.3V10%smd0603
C348 = 1C_470pFCapacitor100V10%0402
D16 = Diode200mA250V
J10 = 2J_ConnectorRJ45_Gigabit
L19 L20 = 1L_NFM21PC474_EMIFilter
R93 R98 R99 R101 R103 R415-R420 R434 = 1R_22OhmResistor1_16W1%0402: MfrNum: MCR01MRTF22R0
R115 R119 R135 R144 R146 R430 = 1R_10KOhmResistor1_10W1%0402
R207 R224-R226 R239 R240 = 1R_33ohmResistor1_16W5%0402
R238 = 1R_1MOhmResistor1_16W0402
R241 R242 = 220ohm1_10W1%smd0402
R112 R116 R128 R129 R131 R132 R137 R138 R140 R393 R398 R399 R428 = 1R_11KOhmResistor1_16W0402
R120 R121 R123-R125 R127 R150-R152 R157 R159-R161 R166 R400 R405 R406 R410 R411 R414 R427 R433 R563 = 1R_2.49KOhmResistor1_16W0402
R413 R562 = 1R_6.04KOhmResistor1_16W0402
R438 = 1R_100KOhmResistor1_16W0402
R439 = 1R_4.7KOhmResistor1_16W0402
R186-R189 R436 R437 R442-R447 R564-R567 = 1R_2.2KOhmResistor1_16W0402
R456 = 1R_10KOhmResistor1_10W1%0402: DescriptiveText: Resistor 11Kohm 1/10W 1% 0402; MfrNum: ERJ-2RKF1102X; PartName: 11Kohm1/10W1%smd0402
R459 = 1R_ZeroOhmResistor1_2W1210
R463 = 1R_150KohmResistor1_16W1%0402
R464 = 1R_118KOhmResistor1_16W0402
R554 = 1R_1KOhmResistor1_16W0402
TP20 TP28-TP32 = 2H_Testpoint_SMD1mmCircle
U20 = 1A_CDCE937
U43 = 1A_DP83867_0: MfrNum: DP83867IRPAPT
U44 = 1A_TPS72011DRV: MfrNum: TPS72011DRVT
U45 = 1A_LMZ10501
U46 U47 = 1A_TPD4E05U06DQA: MfrNum: TPD4E05U06DQAR
Y2 = 1Y_Crystal25MHzABM3
C362 C363 = 1C_4700pFCapacitor50V10%0402
J8 J9 = RJ45_10_100_ETH_W_LED_STACKED
R113 R117 R130 R139 = RESISTOR: Crtd /date: VASANTHA/170516; DescriptiveText: RES 5.76K 1/16W 1% 0402; Mfr: PANASONIC-ECG; MfrNum: ERJ-2RKF5761X; Mistral part number: NSPN00359; Part_type: RESISTORS\FIXED
R114 R118 R133 R134 R136 R141-R143 R145 R389-R392 R394 R395 R397 = 1R_0.2KohmResistor1_8W1%0402: RES SMD 1K OHM 1% 1/10W 0402; DescriptiveText: RES SMD 1K OHM 1% 1/10W 0402; Mfr: Panasonic Electronic Components; MfrNum: ERJ-2RKF1001X; Part Number: RES SMD 1K OHM 1% 1/10W 0402; PartName: RES SMD 1K OHM 1% 1/10W 0402
R122 R126 R153-R156 R158 R162-R165 R167 R396 R402-R404 R407-R409 = 1R_1.96KOhmResistor1_16W0402
R210-R215 R217 R218 R227-R234 = 1R_49.9OhmResistor1_16W0402
R216 R219-R221 = 1R_4.87Kohm1_16W1%smd0402
R449-R452 = 1R_ZeroOhmResistor1_16W0603
R470 R471 R476 R478 R485 R486 R492 R493 = 330ohm1_16W5%smd0402
U16-U19 = 1A_DP83822
U9 = 66AK2G02-ZBB_BGA625: Crtd /date: VASANTHA/090616; DescriptiveText: IC ARM CORTEX AND DSP 32 BIT MICROPROCESSOR BGA625; Mfr: TEXAS INSTRUMENTS; Mistral part number: NSPN00330; Part_type: ICS\DIGITAL\MICROPROCESSOR
C2 = 1C_CAP_4.7uF_X5R_10V_20%_0603
D27 = DIODE_PESD: DIODE 1CH ESD PROTECTION SMD(0402); Crtd /date: VASANTHA/270516; Custom_Duty: 15%; Customs_HS_Code: 85423100; DescriptiveText: DIODE 1CH ESD PROTECTION SMD(0402); Distributor_name: DIGIKEY; Distributor_part_number: 296-30406-1-ND; Height: 0.45MM; Mfr: TEXAS INSTRUMENTS; MfrNum: TPD1E10B06DPYR; Mfr_name: TEXAS INSTRUMENTS; Mfr_part_number: TPD1E10B06DPYR; Mistral Part No: 130014110022-R; Mistral part number: NSPN00395; Package: SMD; Part_type: DIODE\MISC; Project: GALILEO_EVM; RoHS: RoHS; Temperature: -40°C+125°C; Tolerance: NA; Voltage: NA; Wattage: NA; Weight: NA; Datasheet: Y:\MIS_DATABASE\DATASHEETS\ICS\INTERFACE\TPD1E10B06.PDF
J12 = 2C_Conn_microSD_8
U144 = TXS0108EPW_TSSOP20: Crtd /date: VASANTHA/170516; DescriptiveText: IC TRANSLATOR BIDIRECTIONAL VOLTAGE-LEVEL 8BIT TSSOP20; Mfr: TEXAS INSTRUMENTS; Mistral part number: NSPN00383; Part_type: ICS\INTERFACE

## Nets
AGNDFRAME_JACK1: C362.2 J9.SHLD1 J9.SHLD2 J9.SHLD3 J9.SHLD4
AGNDFRAME_JACK2: C363.2 J8.SHLD1 J8.SHLD2 J8.SHLD3 J8.SHLD4
DGND: C2.2 C52.2 C59.2 C66.2 C67.2 C68.2 C69.2 C71.2 C72.2 C74.2 C75.2 C78.2 C79.2 C80.2 C81.2 C82.2 C87.2 C88.2 C89.2 C90.2 C91.1 C93.1 C95.2 C96.2 C97.2 C99.1 C100.1 C101.2 C314.2 C317.2 C318.2 C319.2 C320.2 C322.2 C323.2 C324.2 C325.2 C326.2 C327.2 C328.2 C329.2 C330.2 C331.2 C332.2 C333.2 C334.2 C335.2 C336.2 C337.2 C338.2 C339.2 C340.2 C341.2 C342.2 C343.2 C344.2 C345.2 C346.2 C347.2 C348.2 C349.2 C350.2 C351.2 C354.2 C355.2 C356.2 C357.2 C358.2 C362.1 C363.1 C366.1 C367.2 C409.2 C412.2 C413.2 C414.2 C415.2 C416.2 C417.2 C418.2 C419.2 C420.2 C421.2 C422.2 C423.2 C424.2 D27.2(A) J10.1 J10.12 J10.13 J12.6(VSS) J12.9(GND) J12.11(GND3) J12.12(GND4) J12.13(GND5) J12.14(GND6) J12.15(GND7) J12.16(GND8) L19.2(GND) L20.2(GND) R120.1(P1) R121.1(P1) R122.1(P1) R123.1(P1) R124.1(P1) R125.1(P1) R126.1(P1) R127.1(P1) R150.1(P1) R151.1(P1) R152.1(P1) R153.1(P1) R154.1(P1) R155.1(P1) R156.1(P1) R157.1(P1) R158.1(P1) R159.1(P1) R160.1(P1) R161.1(P1) R162.1(P1) R163.1(P1) R164.1(P1) R165.1(P1) R166.1(P1) R167.1(P1) R216.1(P1) R219.1(P1) R220.1(P1) R221.1(P1) R400.2(P2) R402.1(P1) R403.1(P1) R404.1(P1) R405.1(P1) R406.1(P1) R407.1(P1) R408.1(P1) R409.1(P1) R410.1(P1) R411.1(P1) R414.2(P2) R427.2(P2) R433.2(P2) R439.1(P1) R456.2 R464.1(P1) R507.1(P1) R508.1(P1) R554.2(P2) R563.2(P2) U14.3(GND) U15.3(GND) U16.TPAD(GND) U17.TPAD(GND) U18.TPAD(GND) U19.TPAD(GND) U20.5(GND1) U20.9(GND2) U20.16(GND3) U38.10(VSS) U43.TPAD(GNDPAD) U44.5(GND) U44.TPAD U45.4(SGND) U45.6(PGND) U45.TPAD U46.3(GND) U46.8(GND) U47.3(GND) U47.8(GND) U49.3(GND) U50.3(GND) U51.3(GND) U53.3(GND) U144.11(GND) ; also on sheet 4 5 6 7 8 9 10 11 19 20 21 22 23 24 25 26 27 28 29
V3_3D_PRU0MII0: C357.1 J9.A3 R466.1(P1)
V3_3D_PRU0MII1: C356.1 J9.B3 R465.1(P1)
V3_3D_PRU1MII0: C355.1 J8.A3 R468.1(P1)
V3_3D_PRU1MII1: C358.1 J8.B3 R467.1(P1)
VDD_1V1: C66.1 C67.1 C69.1 C71.1 C344.1 C415.1 C416.1 C417.1 C418.1 C419.1 C420.1 U43.8(VDD1P1) U43.29(VDD1P1) U43.42(VDD1P1) U43.58(VDD1P1) U44.1(VOUT)
VDD_1V8: C366.2 L19.1(IN) R359.1(P1) R506.2(P2) R514.1(P1) R560.1(P1) U144.2(VCCA) ; also on sheet 4 26 27
VDD_1V8_CG: C95.1 L19.3(OUT) U20.3(VDD)
VDD_2V5: C342.1 C346.1 C347.1 C421.1 C422.1 C423.1 C424.1 R459.2(P2) U43.4(VDDA2P5) U43.12(VDDA2P5) U45.3(FB) U45.5(VOUT)
VDD_3V3: C2.1 C52.1 C59.1 C68.1 C74.1 C75.1 C78.1 C79.1 C81.1 C82.1 C87.1 C88.1 C89.1 C90.1 C101.1 C314.1 C317.1 C318.1 C319.1 C320.1 C326.1 C327.1 C328.1 C329.1 C330.1 C331.1 C332.1 C333.1 C334.1 C335.1 C336.1 C337.1 C338.1 C339.1 C340.1 C341.1 C343.1 C345.1 C349.1 C350.1 C351.1 C354.1 C367.1 C409.1 C412.1 C413.1 C414.1 D16.1(Cathode) J12.4(VDD) L20.1(IN) R95.2(P2) R112.2(P2) R113.1 R114.1 R115.2 R116.2(P2) R117.1 R118.1 R119.2 R128.2(P2) R129.2(P2) R130.1 R131.2(P2) R132.2(P2) R133.1 R134.1 R135.2 R136.1 R137.2(P2) R138.2(P2) R139.1 R140.2(P2) R141.1 R142.1 R143.1 R144.2 R145.1 R146.2 R186.1(P1) R187.1(P1) R188.1(P1) R189.2(P2) R193.2(P2) R203.2(P2) R204.2(P2) R205.2(P2) R206.2(P2) R210.1(P1) R211.1(P1) R212.1(P1) R213.1(P1) R214.1(P1) R215.1(P1) R217.1(P1) R218.1(P1) R227.1(P1) R228.1(P1) R229.1(P1) R230.1(P1) R231.1(P1) R232.1(P1) R233.1(P1) R234.1(P1) R377.2(P2) R389.1 R390.1 R391.1 R392.1 R393.2(P2) R394.1 R395.1 R396.2(P2) R397.1 R398.2(P2) R399.1(P1) R413.2(P2) R428.2(P2) R430.2 R436.2(P2) R437.2(P2) R438.2(P2) R442.2(P2) R443.1(P1) R444.1(P1) R445.1(P1) R446.1(P1) R447.2(P2) R449.1(P1) R450.1(P1) R451.1(P1) R452.1(P1) R465.2(P2) R466.2(P2) R467.2(P2) R468.2(P2) R470.2(P2) R471.2(P2) R472.2(P2) R473.2(P2) R474.2(P2) R476.2(P2) R478.2(P2) R485.2(P2) R486.2(P2) R492.2(P2) R493.2(P2) R502.2(P2) R559.1(P1) R562.2(P2) R564.2(P2) R565.2(P2) R566.2(P2) R567.2(P2) U14.5(VCC) U15.5(VCC) U16.21(VDDIO) U17.21(VDDIO) U18.21(VDDIO) U19.21(VDDIO) U38.2(VCC) U38.14(VIO/RFU) U43.23(VDDIO) U43.41(VDDIO) U43.57(VDDIO) U44.4(BIAS) U45.1(EN) U45.7(VIN) U49.5(VCC) U50.5(VCC) U51.5(VCC) U53.5(VCC) U144.19(VCCB) ; also on sheet 4 6 8 9 19 20 21 22 23 24 25 26 27
VDD_3V3_CG: C80.1 C96.1 C97.1 L20.3(OUT) U20.6(VDDOUT1) U20.10(VDDOUT2) U20.13(VDDOUT3)
VDDA1P8_1: U43.17(VDDA1P8_1)
VDDA1P8_2: U43.64(VDDA1P8_2)
ETH0_MDC: R334.1(P1) U43.20(MDC)
ETH0_MDIO: R329.1(P1) R447.1(P1) U43.21(MDIO)
ETH0_RXCLK: R419.1(P1) U43.43(RX_CLK)
ETH0_RXD0: R399.2(P2) R400.1(P1) R418.1(P1) U43.44(RX_D0)
ETH0_RXD1: R417.1(P1) U43.45(RX_D1)
ETH0_RXD2: R416.1(P1) U43.46(RX_D2)
ETH0_RXD3: R415.1(P1) U43.47(RX_D3)
ETH0_RXD4: R413.1(P1) R414.1(P1) U43.48(RX_D4)
ETH0_RXD6: R427.1(P1) R428.1(P1) U43.50(RX_D6)
ETH0_RXD7: R430.1 R433.1(P1) U43.51(RX_D7)
ETH0_RXDV: R434.1(P1) R562.1(P1) R563.1(P1) U43.53(RX_CTRL)
ETH0_TXCLK: R103.1(P1) U43.40(GTX_CLK)
ETH0_TXD0: R420.1(P1) U43.38(TX_D0)
ETH0_TXD1: R99.1(P1) U43.37(TX_D1)
ETH0_TXD2: R98.1(P1) U43.36(TX_D2)
ETH0_TXD3: R101.1(P1) U43.35(TX_D3)
ETH0_TXEN: R93.1(P1) U43.52(TX_CTRL)
ETH_MDIO_CLK: R334.2(P2) U9.U3(MDIO_CLK)
ETH_MDIO_DATA: R329.2(P2) U9.V3(MDIO_DATA)
ETHER0_D0N: J10.10 U43.3(TD_M_A) U46.2(D1-)
ETHER0_D0P: J10.9 U43.2(TD_P_A) U46.1(D1+)
ETHER0_D1N: J10.8 U43.6(TD_M_B) U46.5(D2-)
ETHER0_D1P: J10.7 U43.5(TD_P_B) U46.4(D2+)
ETHER0_D2N: J10.6 U43.11(TD_M_C) U47.2(D1-)
ETHER0_D2P: J10.5 U43.10(TD_P_C) U47.1(D1+)
ETHER0_D3N: J10.4 U43.14(TD_M_D) U47.5(D2-)
ETHER0_D3P: J10.3 U43.13(TD_P_D) U47.4(D2+)
GB_ETH0_INTn: R446.2(P2) U43.60(INT/PWDN)
GB_ETH_RESETn: R146.1 U14.1(A) ; also on sheet 24
GBETH0_RESETn: C72.1 D16.2(Anode) R438.1(P1) U14.4(Y) U43.59(RESET_N)
GIGETH_25MHzCLK: R240.2 U43.19(XI)
GPIO_PR0_MII0_RESETn: R482.2(P2) ; also on sheet 24
GPIO_PR0_MII1_RESETn: R481.2(P2) ; also on sheet 24
GPIO_PR1_MII0_RESETn: R198.2(P2) ; also on sheet 24
GPIO_PR1_MII1_RESETn: R483.2(P2) ; also on sheet 24
I2C_SCL0: R223.2(P2) ; also on sheet 6 8 24
I2C_SDA0: R222.2(P2) ; also on sheet 6 8 24
K2G_MMC1_POW: R514.2(P2) U9.K2(MMC1_POW/GPIO0_71)
K2G_MMC1_SDWP: R359.2(P2) U9.K3(MMC1_SDWP/GPIO0_70)
K2G_PR1MII0_COL: R425.2(P2) U9.B11(PR1_PRU0_GPO9/PR1_PRU0_GPI9/pr1_mii0_col)
K2G_PR1MII0_CRS: R172.2(P2) U9.B12(PR1_PRU0_GPO10/PR1_PRU0_GPI0/pr1_mii0_crs)
K2G_PR1MII0_MRCLK: R174.2(P2) U9.F12(PR1_PRU0_GPO6/PR1_PRU0_GPI6/pr1_mii_mr0_clk)
K2G_PR1MII0_RXD0: R170.2(P2) U9.E10(PR1_PRU0_GPO0/PR1_PRU0_GPI0/pr1_mii0_rxd0)
K2G_PR1MII0_RXD1: R169.2(P2) U9.D10(PR1_PRU0_GPO1/PR1_PRU0_GPI1/pr1_mii0_rxd1)
K2G_PR1MII0_RXD2: R168.2(P2) U9.F10(PR1_PRU0_GPO2/PR1_PRU0_GPI2/pr1_mii0_rxd2)
K2G_PR1MII0_RXD3: R183.2(P2) U9.C11(PR1_PRU0_GPO3/PR1_PRU0_GPI3/pr1_mii0_rxd3)
K2G_PR1MII0_RXDV: R173.2(P2) U9.D11(PR1_PRU0_GPO4/PR1_PRU0_GPI4/pr1_mii0_rxdv)
K2G_PR1MII0_RXER: R171.2(P2) U9.E11(PR1_PRU0_GPO5/PR1_PRU0_GPI5/pr1_mii0_rxer)
K2G_PR1MII0_TXCLK: R385.2(P2) U9.D16(PR1_PRU1_GPO16/PR1_PRU1_GPI16/pr0_mii_mt0_clk)
K2G_PR1MII0_TXD0: R380.2(P2) U9.E15(PR1_PRU1_GPO11/pr1_mii0_txd0)
K2G_PR1MII0_TXD1: R106.2(P2) U9.B16(PR1_PRU1_GPO12/pr1_mii0_txd1)
K2G_PR1MII0_TXD2: R381.2(P2) U9.C16(PR1_PRU1_GPO13/pr1_mii0_txd2)
K2G_PR1MII0_TXD3: R383.2(P2) U9.D17(PR1_PRU1_GPO14/pr1_mii0_txd3)
K2G_PR1MII0_TXEN: R384.2(P2) U9.C18(PR1_PRU1_GPO15/pr1_mii0_txen)
K2G_PR1MII1_COL: R423.2(P2) U9.D15(PR1_PRU1_GPO9/PR1_PRU1_GPI9/pr1_mii1_col)
K2G_PR1MII1_CRS: R179.2(P2) U9.A16(PR1_PRU1_GPO10/PR1_PRU1_GPI0/pr1_mii1_crs)
K2G_PR1MII1_MRCLK: R181.2(P2) U9.F14(PR1_PRU1_GPO6/PR1_PRU1_GPI6/pr1_mii_mr1_clk)
K2G_PR1MII1_RXD0: R177.2(P2) U9.A14(PR1_PRU1_GPO0/PR1_PRU1_GPI0/pr1_mii1_rxd0)
K2G_PR1MII1_RXD1: R176.2(P2) U9.B14(PR1_PRU1_GPO1/PR1_PRU1_GPI1/pr1_mii1_rxd1)
K2G_PR1MII1_RXD2: R175.2(P2) U9.C14(PR1_PRU1_GPO2/PR1_PRU1_GPI2/pr1_mii1_rxd2)
K2G_PR1MII1_RXD3: R184.2(P2) U9.E14(PR1_PRU1_GPO3/PR1_PRU1_GPI3/pr1_mii1_rxd3)
K2G_PR1MII1_RXDV: R180.2(P2) U9.D14(PR1_PRU1_GPO4/PR1_PRU1_GPI4/pr1_mii1_rxdv)
K2G_PR1MII1_RXER: R178.2(P2) U9.A15(PR1_PRU1_GPO5/PR1_PRU1_GPI5/pr1_mii1_rxer)
K2G_PR1MII1_TXCLK: R382.2(P2) U9.C13(PR1_PRU0_GPO16/PR1_PRU0_GPI16/pr1_mii_mt1_clk)
K2G_PR1MII1_TXD0: R104.2(P2) U9.A12(PR1_PRU0_GPO11/pr1_mii1_txd0)
K2G_PR1MII1_TXD1: R108.2(P2) U9.A11(PR1_PRU0_GPO12/pr1_mii1_txd1)
K2G_PR1MII1_TXD2: R105.2(P2) U9.A13(PR1_PRU0_GPO13/pr1_mii1_txd2)
K2G_PR1MII1_TXD3: R107.2(P2) U9.B13(PR1_PRU0_GPO14/pr1_mii1_txd3)
K2G_PR1MII1_TXEN: R379.2(P2) U9.F13(PR1_PRU0_GPO15/pr1_mii1_txen)
K2G_PRU0_MDC: R196.2(P2) R197.2(P2) U9.C10(PR0_MDIO_MDCLK)
K2G_PRU0_MDIO: R201.2(P2) R202.2(P2) R436.1(P1) U9.A10(PR0_MDIO_DATA)
K2G_PRU0MII0_COL: U9.C2(PR0_PRU0_GPO9/PR0_PRU0_GPI9/pr0_mii0_col) ; also on sheet 22
K2G_PRU0MII0_CRS: U9.C3(PR0_PRU0_GPO10/PR0_PRU0_GPI0/pr0_mii0_crs) ; also on sheet 22
K2G_PRU0MII0_MRCLK: U9.B2(PR0_PRU0_GPO6/PR0_PRU0_GPI6/pr0_mii_mr0_clk) ; also on sheet 22
K2G_PRU0MII0_RXD0: U9.D3(PR0_PRU0_GPO0/PR0_PRU0_GPI0/pr0_mii0_rxd0) ; also on sheet 22
K2G_PRU0MII0_RXD1: U9.A2(PR0_PRU0_GPO1/PR0_PRU0_GPI1/pr0_mii0_rxd1) ; also on sheet 22
K2G_PRU0MII0_RXD2: U9.E4(PR0_PRU0_GPO2/PR0_PRU0_GPI2/pr0_mii0_rxd2) ; also on sheet 22
K2G_PRU0MII0_RXD3: U9.B1(PR0_PRU0_GPO3/PR0_PRU0_GPI3/pr0_mii0_rxd3) ; also on sheet 22
K2G_PRU0MII0_RXDV: U9.A3(PR0_PRU0_GPO4/PR0_PRU0_GPI4/pr0_mii0_rxdv) ; also on sheet 22
K2G_PRU0MII0_RXER: U9.E5(PR0_PRU0_GPO5/PR0_PRU0_GPI5/pr0_mii0_rxer) ; also on sheet 22
K2G_PRU0MII0_RXLINK: U9.E6(PR0_PRU0_GPO8/PR0_PRU0_GPI8/pr0_mii0_rxlink) ; also on sheet 22
K2G_PRU0MII0_RXLINK_SW: R494.2(P2) ; also on sheet 22
K2G_PRU0MII0_TXCLK: U9.C9(PR0_PRU1_GPO16/PR0_PRU1_GPI16/pr0_mii_mt0_clk) ; also on sheet 22
K2G_PRU0MII0_TXD0: U9.E9(PR0_PRU1_GPO11/pr0_mii0_txd0) ; also on sheet 22
K2G_PRU0MII0_TXD1: U9.A8(PR0_PRU1_GPO12/pr0_mii0_txd1) ; also on sheet 22
K2G_PRU0MII0_TXD2: U9.B8(PR0_PRU1_GPO13/pr0_mii0_txd2) ; also on sheet 22
K2G_PRU0MII0_TXD3: U9.D9(PR0_PRU1_GPO14/pr0_mii0_txd3) ; also on sheet 22
K2G_PRU0MII0_TXEN: U9.C8(PR0_PRU1_GPO15/pr0_mii0_txen) ; also on sheet 22
K2G_PRU0MII1_COL: U9.B7(PR0_PRU1_GPO9/PR0_PRU1_GPI9/pr0_mii1_col) ; also on sheet 23
K2G_PRU0MII1_CRS: U9.C7(PR0_PRU1_GPO10/PR0_PRU1_GPI0/pr0_mii1_crs) ; also on sheet 23
K2G_PRU0MII1_MRCLK: U9.A7(PR0_PRU1_GPO6/PR0_PRU1_GPI6/pr0_mii_mr1_clk) ; also on sheet 23
K2G_PRU0MII1_RXD0: U9.B5(PR0_PRU1_GPO0/PR0_PRU1_GPI0/pr0_mii1_rxd0) ; also on sheet 23
K2G_PRU0MII1_RXD1: U9.B6(PR0_PRU1_GPO1/PR0_PRU1_GPI1/pr0_mii1_rxd1) ; also on sheet 23
K2G_PRU0MII1_RXD2: U9.D7(PR0_PRU1_GPO2/PR0_PRU1_GPI2/pr0_mii1_rxd2) ; also on sheet 23
K2G_PRU0MII1_RXD3: U9.A6(PR0_PRU1_GPO3/PR0_PRU1_GPI3/pr0_mii1_rxd3) ; also on sheet 23
K2G_PRU0MII1_RXDV: U9.C6(PR0_PRU1_GPO4/PR0_PRU1_GPI4/pr0_mii1_rxdv) ; also on sheet 23
K2G_PRU0MII1_RXER: U9.E8(PR0_PRU1_GPO5/PR0_PRU1_GPI5/pr0_mii1_rxer) ; also on sheet 23
K2G_PRU0MII1_RXLINK: U9.F9(PR0_PRU1_GPO8/PR0_PRU1_GPI8/pr0_mii1_rxlink) ; also on sheet 23
K2G_PRU0MII1_RXLINK_SW: R496.1(P1) ; also on sheet 23
K2G_PRU0MII1_TXCLK: U9.D6(PR0_PRU0_GPO16/PR0_PRU0_GPI16/pr0_mii_mt1_clk) ; also on sheet 23
K2G_PRU0MII1_TXD0: U9.D5(PR0_PRU0_GPO11/pr0_mii1_txd0) ; also on sheet 23
K2G_PRU0MII1_TXD1: U9.B3(PR0_PRU0_GPO12/pr0_mii1_txd1) ; also on sheet 23
K2G_PRU0MII1_TXD2: U9.B4(PR0_PRU0_GPO13/pr0_mii1_txd2) ; also on sheet 23
K2G_PRU0MII1_TXD3: U9.A4(PR0_PRU0_GPO14/pr0_mii1_txd3) ; also on sheet 23
K2G_PRU0MII1_TXEN: U9.E7(PR0_PRU0_GPO15/pr0_mii1_txen) ; also on sheet 23
K2G_PRU1_MDC: R194.2(P2) R195.2(P2) U9.D18(PR1_MDIO_MDCLK)
K2G_PRU1_MDIO: R199.2(P2) R200.2(P2) R437.1(P1) U9.E18(PR1_MDIO_DATA)
K2G_PRU1MII0_RXLINK: R487.1(P1) U9.C12(PR1_PRU0_GPO8/PR1_PRU0_GPI8/pr1_mii0_rxlink)
K2G_PRU1MII1_RXLINK: R489.1(P1) U9.C15(PR1_PRU1_GPO8/PR1_PRU1_GPI8/pr1_mii1_rxlink)
K2G_RGMII0_RD0: R418.2(P2) U9.B24(MII_RXD0/RGMII_RXD0)
K2G_RGMII0_RD1: R417.2(P2) U9.C23(MII_RXD1/RGMII_RXD1)
K2G_RGMII0_RD2: R416.2(P2) U9.B23(MII_RXD2/RGMII_RXD2)
K2G_RGMII0_RD3: R415.2(P2) U9.F22(MII_RXD3/RGMII_RXD3)
K2G_RGMII0_RXCLK: R419.2(P2) U9.A22(MII_RXCLK/RGMII_RXC)
K2G_RGMII0_RXCTL: R434.2(P2) U9.A24(MII_RXDV/RGMII_RXCTL)
K2G_RGMII0_TD0: R420.2(P2) U9.G23(MII_TXD0/RGMII_TXD0)
K2G_RGMII0_TD1: R99.2(P2) U9.G24(MII_TXD1/RGMII_TXD1)
K2G_RGMII0_TD2: R98.2(P2) U9.G25(MII_TXD2/RGMII_TXD2)
K2G_RGMII0_TD3: R101.2(P2) U9.D25(MII_TXD3/RGMII_TXD3)
K2G_RGMII0_TXCLK: R103.2(P2) U9.C25(MII_TXCLK/RGMII_TXC)
K2G_RGMII0_TXCTL: R93.2(P2) U9.H25(MII_TXEN/RGMII_TXCTL)
K2G_SPIMEM_CSn: R90.2(P2) U9.J25(QSPI_CSn0)
MMC1_CLK: U9.J4(MMC1_CLK) U144.7(A6)
MMC1_CMD: U9.J2(MMC1_CMD) U144.6(A5)
MMC1_D0: U9.H3(MMC1_DAT0) U144.1(A1)
MMC1_D1: U9.F5(MMC1_DAT1) U144.3(A2)
MMC1_D2: U9.J5(MMC1_DAT2) U144.4(A3)
MMC1_D3: U9.H4(MMC1_DAT3) U144.5(A4)
MMC_CLK: J12.5(CLOCK) U144.14(B6)
MMC_CMD: J12.3(CMD) U144.15(B5)
MMC_D0: J12.7(DAT0) U144.20(B1)
MMC_D1: J12.8(DAT1) U144.18(B2)
MMC_D2: J12.1(DAT2) U144.17(B3)
MMC_D3: J12.2(CD/DAT3) U144.16(B4)
OE_PRU0MII0_1: U9.H22(QSPI_CSn2/GPIO1_66) ; also on sheet 22
OE_PRU0MII0_2: U9.H21(QSPI_CSn3/GPIO1_67) ; also on sheet 22
PHY_LED_1000n: R241.1 U43.62(LED_1)
PHY_LED_ACTn: R242.1 U43.61(LED_2)
PORZn: R547.2(P2) ; also on sheet 4 6
PR0_ECAP0_ECAP_CAPIN_APWM_O: U9.C24(SPI3_SCSn0/PR0_eCAP0_eCAP_CAPIN_APWM_O) ; also on sheet 24
PR0_EDIO_DATA0: U9.D23(eHRPWM3_SYNCO/PR0_EDIO_DATA0) ; also on sheet 24
PR0_EDIO_DATA1: U9.C22(eHRPWM3_SYNCI/PR0_EDIO_DATA1) ; also on sheet 24
PR0_EDIO_DATA2: U9.B22(eHRPWM3_B/PR0_EDIO_DATA2) ; also on sheet 24
PR0_EDIO_DATA3: U9.A23(eHRPWM3_A/PR0_EDIO_DATA3) ; also on sheet 24
PR0_MII0_25MHzCLK: R207.2 TP30.1 U18.23(XI)
PR0_MII0_INTn: R564.1(P1) U18.8(INTn/PWDNn) ; also on sheet 24
PR0_MII0_RESETn: R205.1(P1) U18.18(RESET_N) U50.4(Y)
PR0_MII1_25MHzCLK: R224.2 TP31.1 U19.23(XI)
PR0_MII1_INTn: R565.1(P1) U19.8(INTn/PWDNn) ; also on sheet 24
PR0_MII1_RESETn: R206.1(P1) U19.18(RESET_N) U49.4(Y)
PR0_UART0RXD: U9.E25(SPI3_SCSn1/PR0_UART0_RXD) ; also on sheet 24
PR0_UART0TXD: U9.E24(SPI3_CLK/PR0_UART0_TXD) ; also on sheet 24
PR1_MII0_25MHzCLK: R225.2 TP28.1 U16.23(XI)
PR1_MII0_INTn: R566.1(P1) U16.8(INTn/PWDNn) ; also on sheet 24
PR1_MII0_RESETn: R203.1(P1) U15.4(Y) U16.18(RESET_N)
PR1_MII1_25MHzCLK: R239.2 TP29.1 U17.23(XI)
PR1_MII1_INTn: R567.1(P1) U17.8(INTn/PWDNn) ; also on sheet 24
PR1_MII1_RESETn: R204.1(P1) U17.18(RESET_N) U51.4(Y)
PR1MII0_MDC: R194.1(P1) U16.20(MDC)
PR1MII0_MDIO: R199.1(P1) U16.19(MDIO)
PR1MII1_MDC: R195.1(P1) U17.20(MDC)
PR1MII1_MDIO: R200.1(P1) U17.19(MDIO)
PRU0_MII0_COL: R132.1(P1) R154.2(P2) U18.29(COL) ; also on sheet 22
PRU0_MII0_CRS: R134.2 R156.2(P2) U18.27(CRS) ; also on sheet 22
PRU0_MII0_MDC: R196.1(P1) U18.20(MDC)
PRU0_MII0_MDIO: R201.1(P1) U18.19(MDIO)
PRU0_MII0_RXCLK: U18.25(RX_CLK) ; also on sheet 22
PRU0_MII0_RXD0: R131.1(P1) R153.2(P2) U18.30(RX_D0) ; also on sheet 22
PRU0_MII0_RXD1: R130.2 R152.2(P2) U18.31(RX_D1) ; also on sheet 22
PRU0_MII0_RXD2: R129.1(P1) R151.2(P2) U18.32(RX_D2) ; also on sheet 22
PRU0_MII0_RXD3: R128.1(P1) R150.2(P2) U18.1(RX_D3) ; also on sheet 22
PRU0_MII0_RXDV: R135.1 R157.2(P2) U18.26(RX_DV) ; also on sheet 22
PRU0_MII0_RXERR: R133.2 R155.2(P2) U18.28(RX_ER) ; also on sheet 22
PRU0_MII0_TXCLK: U18.2(TX_CLK) ; also on sheet 22
PRU0_MII0_TXD0: U18.4(TX_D0) ; also on sheet 22
PRU0_MII0_TXD1: U18.5(TX_D1) ; also on sheet 22
PRU0_MII0_TXD2: U18.6(TX_D2) ; also on sheet 22
PRU0_MII0_TXD3: U18.7(TX_D3) ; also on sheet 22
PRU0_MII0_TXEN: U18.3(TX_EN) ; also on sheet 22
PRU0MII0_LINKLED: R136.2 R158.2(P2) R443.2(P2) R494.1(P1) R495.2(P2) U18.17(LED_0)
PRU0MII0_RDN: J9.A2 R231.2(P2) U18.9(RD_M)
PRU0MII0_RDP: J9.A1 R232.2(P2) U18.10(RD_P)
PRU0MII0_SPEEDLED: R188.2(P2) R477.2(P2) U18.24(LED_1)
PRU0MII0_TDN: J9.A8 R214.2(P2) U18.11(TD_M)
PRU0MII0_TDP: J9.A7 R215.2(P2) U18.12(TD_P)
PRU0MII1_COL: R141.2 R163.2(P2) U19.29(COL) ; also on sheet 23
PRU0MII1_CRS: R143.2 R165.2(P2) U19.27(CRS) ; also on sheet 23
PRU0MII1_LINKLED: R145.2 R167.2(P2) R442.1(P1) R496.2(P2) R497.2(P2) U19.17(LED_0)
PRU0MII1_MDC: R197.1(P1) U19.20(MDC)
PRU0MII1_MDIO: R202.1(P1) U19.19(MDIO)
PRU0MII1_RDN: J9.B2 R233.2(P2) U19.9(RD_M)
PRU0MII1_RDP: J9.B1 R234.2(P2) U19.10(RD_P)
PRU0MII1_RXCLK: U19.25(RX_CLK) ; also on sheet 23
PRU0MII1_RXD0: R140.1(P1) R162.2(P2) U19.30(RX_D0) ; also on sheet 23
PRU0MII1_RXD1: R139.2 R161.2(P2) U19.31(RX_D1) ; also on sheet 23
PRU0MII1_RXD2: R138.1(P1) R160.2(P2) U19.32(RX_D2) ; also on sheet 23
PRU0MII1_RXD3: R137.1(P1) R159.2(P2) U19.1(RX_D3) ; also on sheet 23
PRU0MII1_RXDV: R144.1 R166.2(P2) U19.26(RX_DV) ; also on sheet 23
PRU0MII1_RXERR: R142.2 R164.2(P2) U19.28(RX_ER) ; also on sheet 23
PRU0MII1_SPEEDLED: R189.1(P1) R491.2(P2) U19.24(LED_1)
PRU0MII1_TDN: J9.B8 R217.2(P2) U19.11(TD_M)
PRU0MII1_TDP: J9.B7 R218.2(P2) U19.12(TD_P)
PRU0MII1_TXCLK: U19.2(TX_CLK) ; also on sheet 23
PRU0MII1_TXD0: U19.4(TX_D0) ; also on sheet 23
PRU0MII1_TXD1: U19.5(TX_D1) ; also on sheet 23
PRU0MII1_TXD2: U19.6(TX_D2) ; also on sheet 23
PRU0MII1_TXD3: U19.7(TX_D3) ; also on sheet 23
PRU0MII1_TXEN: U19.3(TX_EN) ; also on sheet 23
PRU1MII0_COL: R396.1(P1) R409.2(P2) R425.1(P1) U16.29(COL)
PRU1MII0_CRS: R172.1(P1) R395.2 R408.2(P2) U16.27(CRS)
PRU1MII0_LINKLED: R394.2 R407.2(P2) R445.2(P2) R487.2(P2) R488.2(P2) U16.17(LED_0)
PRU1MII0_RDN: J8.A2 R227.2(P2) U16.9(RD_M)
PRU1MII0_RDP: J8.A1 R228.2(P2) U16.10(RD_P)
PRU1MII0_RXCLK: R174.1(P1) U16.25(RX_CLK)
PRU1MII0_RXD0: R170.1(P1) R397.2 R410.2(P2) U16.30(RX_D0)
PRU1MII0_RXD1: R113.2 R121.2(P2) R169.1(P1) U16.31(RX_D1)
PRU1MII0_RXD2: R168.1(P1) R398.1(P1) R411.2(P2) U16.32(RX_D2)
PRU1MII0_RXD3: R112.1(P1) R120.2(P2) R183.1(P1) U16.1(RX_D3)
PRU1MII0_RXDV: R115.1 R123.2(P2) R173.1(P1) U16.26(RX_DV)
PRU1MII0_RXERR: R114.2 R122.2(P2) R171.1(P1) U16.28(RX_ER)
PRU1MII0_SPEEDLED: R186.2(P2) R475.1(P1) U16.24(LED_1)
PRU1MII0_TDN: J8.A8 R210.2(P2) U16.11(TD_M)
PRU1MII0_TDP: J8.A7 R211.2(P2) U16.12(TD_P)
PRU1MII0_TXCLK: R385.1(P1) U16.2(TX_CLK)
PRU1MII0_TXD0: R380.1(P1) U16.4(TX_D0)
PRU1MII0_TXD1: R106.1(P1) U16.5(TX_D1)
PRU1MII0_TXD2: R381.1(P1) U16.6(TX_D2)
PRU1MII0_TXD3: R383.1(P1) U16.7(TX_D3)
PRU1MII0_TXEN: R384.1(P1) U16.3(TX_EN)
PRU1MII1_COL: R391.2 R404.2(P2) R423.1(P1) U17.29(COL)
PRU1MII1_CRS: R179.1(P1) R390.2 R403.2(P2) U17.27(CRS)
PRU1MII1_LINKLED: R389.2 R402.2(P2) R444.2(P2) R489.2(P2) R490.1(P1) U17.17(LED_0)
PRU1MII1_RDN: J8.B2 R229.2(P2) U17.9(RD_M)
PRU1MII1_RDP: J8.B1 R230.2(P2) U17.10(RD_P)
PRU1MII1_RXCLK: R181.1(P1) U17.25(RX_CLK)
PRU1MII1_RXD0: R177.1(P1) R392.2 R405.2(P2) U17.30(RX_D0)
PRU1MII1_RXD1: R117.2 R125.2(P2) R176.1(P1) U17.31(RX_D1)
PRU1MII1_RXD2: R175.1(P1) R393.1(P1) R406.2(P2) U17.32(RX_D2)
PRU1MII1_RXD3: R116.1(P1) R124.2(P2) R184.1(P1) U17.1(RX_D3)
PRU1MII1_RXDV: R119.1 R127.2(P2) R180.1(P1) U17.26(RX_DV)
PRU1MII1_RXERR: R118.2 R126.2(P2) R178.1(P1) U17.28(RX_ER)
PRU1MII1_SPEEDLED: R187.2(P2) R484.1(P1) U17.24(LED_1)
PRU1MII1_TDN: J8.B8 R212.2(P2) U17.11(TD_M)
PRU1MII1_TDP: J8.B7 R213.2(P2) U17.12(TD_P)
PRU1MII1_TXCLK: R382.1(P1) U17.2(TX_CLK)
PRU1MII1_TXD0: R104.1(P1) U17.4(TX_D0)
PRU1MII1_TXD1: R108.1(P1) U17.5(TX_D1)
PRU1MII1_TXD2: R105.1(P1) U17.6(TX_D2)
PRU1MII1_TXD3: R107.1(P1) U17.7(TX_D3)
PRU1MII1_TXEN: R379.1(P1) U17.3(TX_EN)
QSPI_CLK: R83.1(P1) R86.2(P2) R87.1(P1)
QSPICLK: R83.2(P2) U9.K25(QSPI_CLK)
QSPID0: R96.2(P2) U9.J23(QSPI_D0)
QSPID1: R368.2(P2) U9.J22(QSPI_D1)
QSPID2: R365.2(P2) U9.J21(QSPI_D2)
QSPID3: R92.2(P2) U9.J24(QSPI_D3)
QSPIRCLK: R87.2(P2) U9.K24(QSPI_RCLK)
RESETSTATZ: R546.2(P2) U14.2(B) U15.2(B) U49.2(B) U50.2(B) U51.2(B) ; also on sheet 6
SD_DETECT: D27.1(K) J12.10(CD) R560.2(P2) U9.J3(MMC1_SDCD/GPIO0_69)
SHIELD_EARTH1: C99.2 C100.2 J10.SHLD1 J10.SHLD2
SPIMEM_CLK: R86.1(P1) U38.16(SCK)
SPIMEM_CSn: R90.1(P1) R559.2(P2) U38.7(~{CS})
SPIMEM_D0: R96.1(P1) U38.15(SI/IO0)
SPIMEM_D1: R368.1(P1) U38.8(SO/IO1)
SPIMEM_D2: R95.1(P1) R365.1(P1) U38.9(~{WP}/IO2)
SPIMEM_D3: R92.1(P1) R377.1(P1) U38.1(~{HOLD}/IO3)
SPIMEM_RST: R502.1(P1) U53.1(A) ; also on sheet 9
SPIMEM_RST_AND: U38.3(~{RESET}) U53.4(Y)
SYSCLK: R226.2 ; also on sheet 26
VADD33_PRU0MII0: C323.1 R450.2(P2) U18.14(AVD33)
VADD33_PRU0MII1: C322.1 R449.2(P2) U19.14(AVD33)
VADD33_PRU1MII0: C325.1 R452.2(P2) U16.14(AVD33)
VADD33_PRU1MII1: C324.1 R451.2(P2) U17.14(AVD33)
N29337752: R473.1(P1) R482.1(P1) U50.1(A)
N29337927: R216.2(P2) U18.16(RBIAS)
N29340157: R219.2(P2) U19.16(RBIAS)
N29342624: R220.2(P2) U16.16(RBIAS)
N29345736: R221.2(P2) U17.16(RBIAS)
N30324047: C348.1 R463.1(P1) R464.2(P2) U45.2(VCON)
N30324076: R459.1(P1) U44.3(EN) U44.6(VIN)
N30333662: TP32.1 U43.22(CLK_OUT)
N30334759: C93.2 R238.2(P2) U20.1(Xin/CLK) Y2.2
N30334761: C91.2 R236.2(P2) R238.1(P1) Y2.1
N30334787: R236.1(P1) U20.20(XOUT)
N30334814: R223.1(P1) U20.18(S2/SCL)
N30334816: R222.1(P1) U20.19(S1/SDA)
N30336090: R456.1 U43.15(RBIAS)
N30336904: R439.2(P2) U43.24(JTAG_TRSTN)
N31099107: R193.1(P1) R198.1(P1) U15.1(A)
N31155190: R472.1(P1) R481.1(P1) U49.1(A)
N31155632: R474.1(P1) R483.1(P1) U51.1(A)
N31619643: J10.14 R241.2
N31638936: R240.1 U20.8(Y5)
N31638949: R225.1 U20.14(Y3)
N31638951: R239.1 U20.7(Y4)
N31638981: R207.1 U20.17(Y1)
N31638983: R224.1 U20.15(Y2)
N31639458: R226.1 U20.12(Y6)
N31693310: J10.11 R242.2
N33250687: R507.2(P2) U144.8(A7) U144.9(A8)
N33250697: R508.2(P2) U144.12(B8) U144.13(B7)
N33252323: R506.1(P1) U144.10(OE)
N33359703: R463.2(P2) U45.8(VREF)
N33457471: J9.17 R492.1(P1)
N33457473: J9.18 R477.1(P1)
N33457510: J9.15 R471.1(P1)
N33457736: J9.13 R493.1(P1)
N33457738: J9.14 R491.1(P1)
N33457786: J9.11 R478.1(P1)
N33458005: J8.15 R470.1(P1)
N33458040: J8.17 R485.1(P1)
N33458042: J8.18 R475.2(P2)
N33458468: J8.13 R486.1(P1)
N33458479: J8.11 R476.1(P1)
N33458512: J8.14 R484.2(P2)
N33860383: R546.1(P1) R547.1(P1) U53.2(B)
N33863701: R554.1(P1) TP20.1 U9.D24(RMII_REFCLK)
N34377344: J9.16 R495.1(P1)
N34378426: J9.12 R497.1(P1)
N34379018: J8.16 R488.1(P1)
N34380172: J8.12 R490.2(P2)

Not connected (* = marked no-connect by the designer): J8 A4* A5* A6* A9* A10* B4* B5* B6* B9* B10*; J9 A4* A5* A6* A9* A10* B4* B5* B6* B9* B10*; J10 2*; U9 B25(MII_COL)* E3(MMC1_DAT4) F4(MMC1_DAT6) F23(MII_RXER/RMII_RXER)* F24(SPI3_SIMO)* F25(SPI3_SOMI)* G4(MMC1_DAT5) G5(MMC1_DAT7) G22(MII_CRS)* H23(QSPI_CSn1)* H24(MII_TXER)*; U16 13(NC)* 15(NC1)* 22(XO)*; U17 13(NC)* 15(NC1)* 22(XO)*; U18 13(NC)* 15(NC1)* 22(XO)*; U19 13(NC)* 15(NC1)* 22(XO)*; U20 2(S0)* 4(Vctr)* 11(Y7)*; U38 4(NC4)* 5(NC5)* 6(NC6)* 11(NC11)* 12(NC12)* 13(NC13)*; U43 1(Reserved1)* 7(Reserved2)* 9(Reserved3)* 16(Reserved4)* 18(XO)* 25(JTAG_CLK)* 26(JTAG_TDO)* 27(JTAG_TMS)* 28(JTAG_TDI)* 30(TX_CLK)* 31(TX_D7)* 32(TX_D6)* 33(TX_D5)* 34(TX_D4)* 39(TX_ER)* 49(RX_D5)* 54(RX_ER)* 55(COL)* 56(CRS)* 63(LED_0)*; U44 2(NC)*; U46 6(NC6)* 7(NC7)* 9(NC9)* 10(NC10)*; U47 6(NC6)* 7(NC7)* 9(NC9)* 10(NC10)*

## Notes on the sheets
sheet 12
- QSPI Flash
sheet 13
- GIGABIT ETHERNET
- ETHERNET CLOCK GENERATION
- STRAPPING RESISTORS
- GIG ETHERNET RESET
- PHY_ADD0  = 0 ; PHY_ADD1 =0 -> MODE 1
- ANEG_SEL1 = 0 ; PHY_ADD4 =0 -> MODE 1
- CLKOUT DISABLE
- RGMII ; AMDIX  ENABLE
- MODE 1
- PHY ADD = 00000
- I2C Address = 0x6Dh
- 2.5V Power
- 1.1V Power
sheet 14
- ETHERNET 0
- RESISTOR STRAPPING
- ETHERNET RESET
- PHY ADD = 00000
sheet 15
- ETHERNET 1
- ETHERNET RESET
- RESISTOR STRAPPING
- PHY ADD = 00001
sheet 16
- ETHERNET 2
- ETHERNET RESET
- RESISTOR STRAPPING
- PHY ADD = 00010
sheet 17
- ETHERNET 3
- ETHERNET RESET
- RESISTOR STRAPPING
- PHY ADD = 00011
sheet 18
- SD/MMC1 Port
- SD/MMC1 1.8V to 3.3V VOLTAGE TRANSLATION
